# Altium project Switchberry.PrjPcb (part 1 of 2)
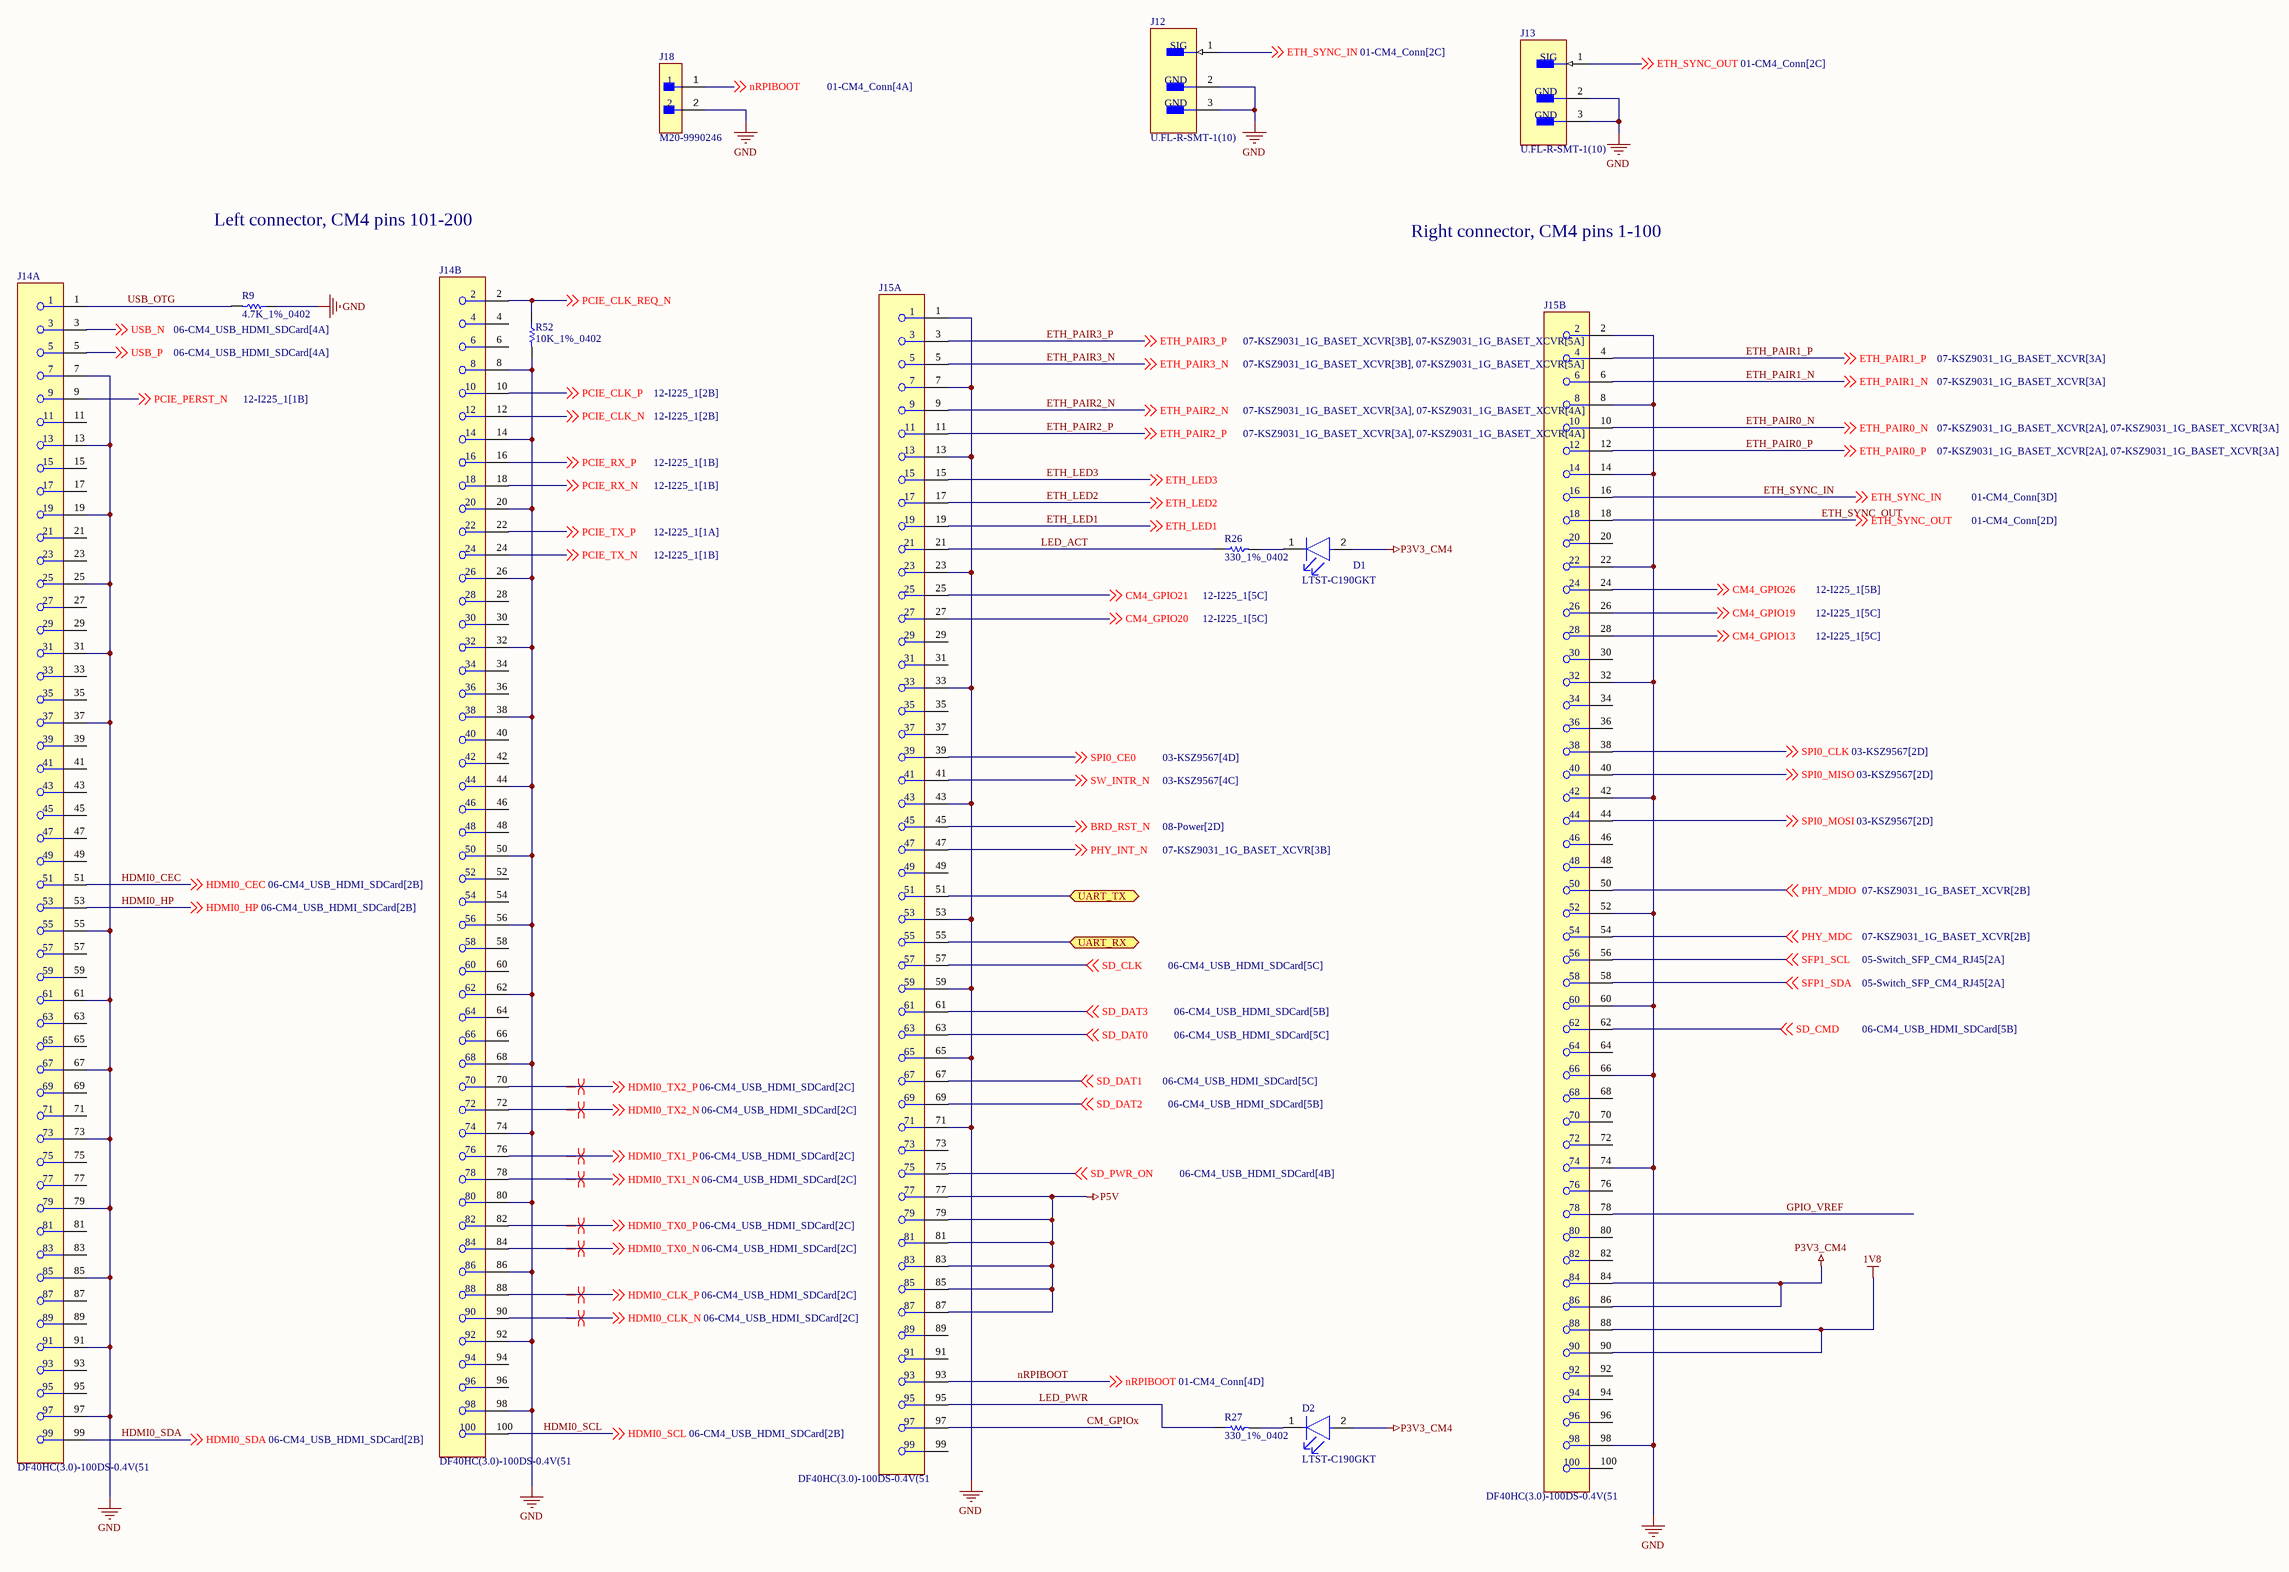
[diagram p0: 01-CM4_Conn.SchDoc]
13 sheets, 431 parts. Net scope: global (net labels, ports and power ports of the same name join across sheets).
Board file: Switchberry.PcbDoc
Sheets:
  01-CM4_Conn.SchDoc
  02-Clocks.SchDoc
  03-KSZ9567.SchDoc
  04-Switch_RJ45.SchDoc
  05-Switch_SFP_CM4_RJ45.SchDoc
  06-CM4_USB_HDMI_SDCard.SchDoc
  07-KSZ9031_1G_BASET_XCVR.SchDoc
  08-Power.SchDoc
  09-Switch_Power_Filters.SchDoc
  10-RJ45_Protection.SchDoc
  11-Switch_Strapping.SchDoc
  12-I225_1.SchDoc
  13-I225_2.SchDoc

## Sheet 01-CM4_Conn.SchDoc
size C; SheetNumber: 1; SheetTotal: 13

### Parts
D1  LTST-C190GKT  [FP-LTST-C190GKT-MFG]
D2  LTST-C190GKT  [FP-LTST-C190GKT-MFG]
J12  U.FL-R-SMT-1(10)  [FP-U_FL-R-SMT-1_10-MFG]
J13  U.FL-R-SMT-1(10)  [FP-U_FL-R-SMT-1_10-MFG]
J14  DF40HC(3.0)-100DS-0.4V(51  [FP-DF40HC_3_0_-100DS-0_4V-MFG]  (parts A,B of 2)
J15  DF40HC(3.0)-100DS-0.4V(51  [FP-DF40HC_3_0_-100DS-0_4V-MFG]  (parts A,B of 2)
J18  M20-9990246  [FP-M20-9990246-MFG]
R9  4.7K_1%_0402  [RESC1005X40X25NL10T10]
R26  330_1%_0402  [RESC1005X40X25NL10T10]
R27  330_1%_0402  [RESC1005X40X25NL10T10]
R52  10K_1%_0402  [RESC1005X40X25NL10T10]

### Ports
UART_RX (bidir), UART_TX (bidir)

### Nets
1V8: J15.88 J15.90
GND: J12.2(GND) J12.3(GND) J13.2(GND) J13.3(GND) J14.7 J14.8 J14.13 J14.14 J14.19 J14.20 J14.25 J14.26 J14.31 J14.32 J14.37 J14.38 J14.44 J14.50 J14.55 J14.56 J14.61 J14.62 J14.67 J14.68 J14.73 J14.74 J14.79 J14.80 J14.85 J14.86 J14.91 J14.92 J14.97 J14.98 J15.1 J15.2 J15.7 J15.8 J15.13 J15.14 J15.22 J15.23 J15.32 J15.33 J15.42 J15.43 J15.52 J15.53 J15.59 J15.60 J15.65 J15.66 J15.71 J15.74 J15.98 J18.2 R9.1 R52.2
P3V3_CM4: D1.2(A) D2.2(A) J15.84 J15.86
P5V: J15.77 J15.79 J15.81 J15.83 J15.85 J15.87
BRD_RST_N: J15.45 ; off-sheet BRD_RST_N
CM4_GPIO13: J15.28 ; off-sheet CM4_GPIO13
CM4_GPIO19: J15.26 ; off-sheet CM4_GPIO19
CM4_GPIO20: J15.27 ; off-sheet CM4_GPIO20
CM4_GPIO21: J15.25 ; off-sheet CM4_GPIO21
CM4_GPIO26: J15.24 ; off-sheet CM4_GPIO26
CM_GPIOx: J15.97
ETH_LED1: J15.19 ; off-sheet ETH_LED1
ETH_LED2: J15.17 ; off-sheet ETH_LED2
ETH_LED3: J15.15 ; off-sheet ETH_LED3
ETH_PAIR0_N: J15.10 ; off-sheet ETH_PAIR0_N
ETH_PAIR0_P: J15.12 ; off-sheet ETH_PAIR0_P
ETH_PAIR1_N: J15.6 ; off-sheet ETH_PAIR1_N
ETH_PAIR1_P: J15.4 ; off-sheet ETH_PAIR1_P
ETH_PAIR2_N: J15.9 ; off-sheet ETH_PAIR2_N
ETH_PAIR2_P: J15.11 ; off-sheet ETH_PAIR2_P
ETH_PAIR3_N: J15.5 ; off-sheet ETH_PAIR3_N
ETH_PAIR3_P: J15.3 ; off-sheet ETH_PAIR3_P
ETH_SYNC_IN: J12.1(SIG) J15.16 ; off-sheet ETH_SYNC_IN
ETH_SYNC_OUT: J13.1(SIG) J15.18 ; off-sheet ETH_SYNC_OUT
GPIO_VREF: J15.78
HDMI0_CEC: J14.51 ; off-sheet HDMI0_CEC
HDMI0_CLK_N: J14.90 ; off-sheet HDMI0_CLK_N
HDMI0_CLK_P: J14.88 ; off-sheet HDMI0_CLK_P
HDMI0_HP: J14.53 ; off-sheet HDMI0_HP
HDMI0_SCL: J14.100 ; off-sheet HDMI0_SCL
HDMI0_SDA: J14.99 ; off-sheet HDMI0_SDA
HDMI0_TX0_N: J14.84 ; off-sheet HDMI0_TX0_N
HDMI0_TX0_P: J14.82 ; off-sheet HDMI0_TX0_P
HDMI0_TX1_N: J14.78 ; off-sheet HDMI0_TX1_N
HDMI0_TX1_P: J14.76 ; off-sheet HDMI0_TX1_P
HDMI0_TX2_N: J14.72 ; off-sheet HDMI0_TX2_N
HDMI0_TX2_P: J14.70 ; off-sheet HDMI0_TX2_P
LED_ACT: J15.21 R26.1
LED_PWR: J15.95 R27.1
nRPIBOOT: J15.93 J18.1 ; off-sheet nRPIBOOT
PCIE_CLK_N: J14.12 ; off-sheet PCIE_CLK_N
PCIE_CLK_P: J14.10 ; off-sheet PCIE_CLK_P
PCIE_CLK_REQ_N: J14.2 R52.1 ; off-sheet PCIE_CLK_REQ_N
PCIE_PERST_N: J14.9 ; off-sheet PCIE_PERST_N
PCIE_RX_N: J14.18 ; off-sheet PCIE_RX_N
PCIE_RX_P: J14.16 ; off-sheet PCIE_RX_P
PCIE_TX_N: J14.24 ; off-sheet PCIE_TX_N
PCIE_TX_P: J14.22 ; off-sheet PCIE_TX_P
PHY_INT_N: J15.47 ; off-sheet PHY_INT_N
PHY_MDC: J15.54 ; off-sheet PHY_MDC
PHY_MDIO: J15.50 ; off-sheet PHY_MDIO
SD_CLK: J15.57 ; off-sheet SD_CLK
SD_CMD: J15.62 ; off-sheet SD_CMD
SD_DAT0: J15.63 ; off-sheet SD_DAT0
SD_DAT1: J15.67 ; off-sheet SD_DAT1
SD_DAT2: J15.69 ; off-sheet SD_DAT2
SD_DAT3: J15.61 ; off-sheet SD_DAT3
SD_PWR_ON: J15.75 ; off-sheet SD_PWR_ON
SFP1_SCL: J15.56 ; off-sheet SFP1_SCL
SFP1_SDA: J15.58 ; off-sheet SFP1_SDA
SPI0_CE0: J15.39 ; off-sheet SPI0_CE0
SPI0_CLK: J15.38 ; off-sheet SPI0_CLK
SPI0_MISO: J15.40 ; off-sheet SPI0_MISO
SPI0_MOSI: J15.44 ; off-sheet SPI0_MOSI
SW_INTR_N: J15.41 ; off-sheet SW_INTR_N
USB_N: J14.3 ; off-sheet USB_N
USB_OTG: J14.1 R9.2
USB_P: J14.5 ; off-sheet USB_P
NetD1_1: D1.1(C) R26.2
NetD2_1: D2.1(C) R27.2
NetJ15_51: J15.51 ; port UART_TX
NetJ15_55: J15.55 ; port UART_RX

Not connected (* = marked no-connect by the designer): J14 4 6 11 15 17 21 23 27 28 29 30 33 34 35 36 39 40 41 42 43 45 46 47 48 49 52 54 57 58 59 60 63 64 65 66 69 71 75 77 81 83 87 89 93 94 95 96; J15 20 29 30 31 34 35 36 37 46 48 49 64 68 70 72 73 76 80 82 89 91 92 94 96 99 100

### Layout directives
differential pair: HDMI0_CLK_N, HDMI0_CLK_P, HDMI0_TX0_N, HDMI0_TX0_P, HDMI0_TX1_N, HDMI0_TX1_P, HDMI0_TX2_N, HDMI0_TX2_P

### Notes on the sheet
- Left connector, CM4 pins 101-200
- Right connector, CM4 pins 1-100

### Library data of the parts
D1 D2 = CMP-22017-000005-2: LED GREEN CLEAR CHIP SMD; Dominant Wavelength: 569nm; Reverse Voltage: 5V; Lens Color: Colorless; Viewing Angle: 130°; Voltage: 2V; Forward Current: 30mA; Power Dissipation: 100mW; Luminous Intensity: 6mcd; Number of LEDs: 1; Forward Voltage: 2.1V; Wavelength: 565nm; Test Current: 10mA
J12 J13 = CMP-2000-05152-3: CONN U.FL RCPT STR 50 OHM SMD; Max Frequency: 6GHz; Connector Type: Coaxial; Body Plating: Silver; Body Material: Bronze; Impedance: 50R; Dielectric Material: Polymer; Insulation Resistance: 500MR; Gender: Male
J14 J15 = CMP-11605-000071-1: CONN RCPT 100POS SMD GOLD; Pitch: 0.016inch; Number of Positions: 100; Connector Type: Receptacle
J18 = CMP-15831-000009-1: CONN HEADER VERT 2POS 2.54MM; Manufacturer: Harwin; Conn Gender: Male; Conn Orientation: Vertical; Number Of Contacts: 2; Current Rating: 3A
R9 = CMP-2002-05217-1: Manufacturer: Bourns; Part Number: CR0402-FX-4701GLF
R26 R27 = CMP-2002-05853-1: Manufacturer: Panasonic; Part Number: ERA-2AED331X
R52 = CMP-2002-04694-1: Manufacturer: Bourns; Part Number: CR0402-FX-1002GLF

## Sheet 02-Clocks.SchDoc
size A; SheetNumber: 2; SheetTotal: 11
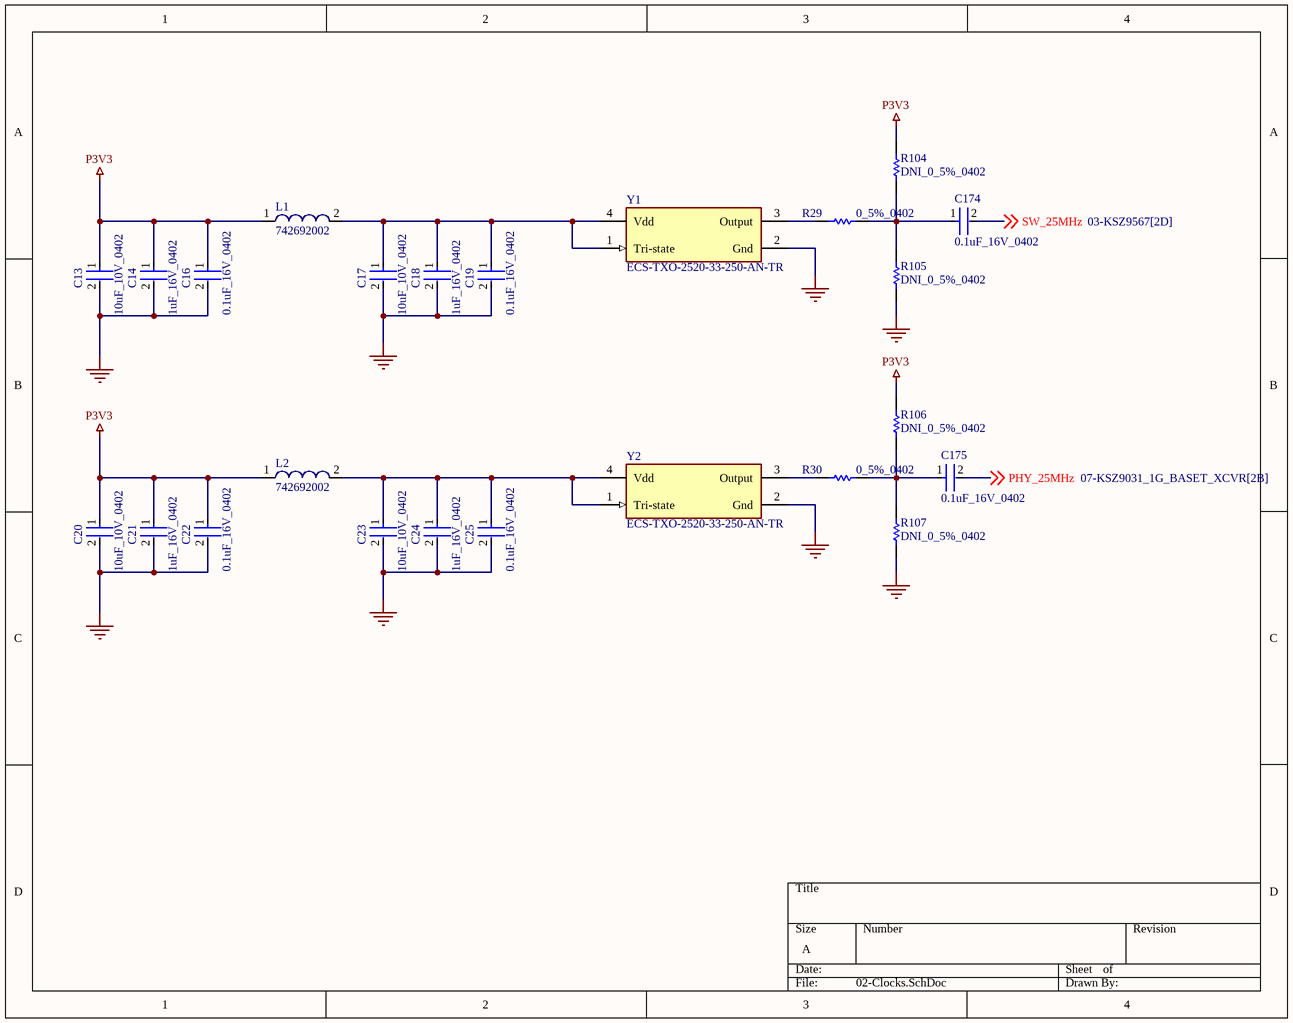
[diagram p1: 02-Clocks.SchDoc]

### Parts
C13  10uF_10V_0402  [FP-CL05A106MP5NUNC-MFG]
C14  1uF_16V_0402  [FP-0402-L_1_0_0_05-W_0_5-IPC_A]
C16  0.1uF_16V_0402  [FP-C0402-BB-MFG]
C17  10uF_10V_0402  [FP-CL05A106MP5NUNC-MFG]
C18  1uF_16V_0402  [FP-0402-L_1_0_0_05-W_0_5-IPC_A]
C19  0.1uF_16V_0402  [FP-C0402-BB-MFG]
C20  10uF_10V_0402  [FP-CL05A106MP5NUNC-MFG]
C21  1uF_16V_0402  [FP-0402-L_1_0_0_05-W_0_5-IPC_A]
C22  0.1uF_16V_0402  [FP-C0402-BB-MFG]
C23  10uF_10V_0402  [FP-CL05A106MP5NUNC-MFG]
C24  1uF_16V_0402  [FP-0402-L_1_0_0_05-W_0_5-IPC_A]
C25  0.1uF_16V_0402  [FP-C0402-BB-MFG]
C174  0.1uF_16V_0402  [FP-C0402-BB-MFG]
C175  0.1uF_16V_0402  [FP-C0402-BB-MFG]
L1  742692002  [WE-TMSB 0201]
L2  742692002  [WE-TMSB 0201]
R29  0_5%_0402  [RESC1005X40X25NL05T10]
R30  0_5%_0402  [RESC1005X40X25NL05T10]
R104  DNI_0_5%_0402  [RESC1005X40X25NL05T10]  (no BOM)
R105  DNI_0_5%_0402  [RESC1005X40X25NL05T10]  (no BOM)
R106  DNI_0_5%_0402  [RESC1005X40X25NL05T10]  (no BOM)
R107  DNI_0_5%_0402  [RESC1005X40X25NL05T10]  (no BOM)
Y1  ECS-TXO-2520-33-250-AN-TR  [FP-ECS-TXO-2520-MFG]
Y2  ECS-TXO-2520-33-250-AN-TR  [FP-ECS-TXO-2520-MFG]

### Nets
GND: C13.2 C14.2 C16.2 C17.2 C18.2 C19.2 C20.2 C21.2 C22.2 C23.2 C24.2 C25.2 R105.1 R107.1 Y1.2(Gnd) Y2.2(Gnd)
P3V3: C13.1 C14.1 C16.1 C20.1 C21.1 C22.1 L1.1 L2.1 R104.2 R106.2
PHY_25MHz: C175.2 ; off-sheet PHY_25MHz
SW_25MHz: C174.2 ; off-sheet SW_25MHz
NetC17_1: C17.1 C18.1 C19.1 L1.2 Y1.1(Tri-state) Y1.4(Vdd)
NetC23_1: C23.1 C24.1 C25.1 L2.2 Y2.1(Tri-state) Y2.4(Vdd)
NetC174_1: C174.1 R29.2 R104.1 R105.2
NetC175_1: C175.1 R30.2 R106.1 R107.2
NetR29_1: R29.1 Y1.3(Output)
NetR30_1: R30.1 Y2.3(Output)

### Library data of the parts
C13 C17 C20 C23 = CMP-13271-000002-1: CAP CER 10UF 10V X5R 0402; Manufacturer Part Number: CL05A106MP5NUNC; Manufacturer: Samsung; Temperature Coefficient: 15%; Tolerance: 20%; Material: Ceramic
C14 C18 C21 C24 = CMP-14477-000104-2: None; Tolerance: 10%; Voltage Rating: 16V; Dielectric: X5R; Capacitance: 1uF
C16 C19 C22 C25 C174 C175 = CMP-1034-02068-3: CAP CER 0.1UF 16V 5% X7R 0402; Manufacturer: Kemet; Manufacturer Part Number: C0402C104J4RACTU; Value: 0.10 μF; Temperature Coefficient: 15%; Tolerance: 0.05; Material: Ceramic
L1 L2 = CMP-1490-00001-1: Tiny Multilayer Suppression  Bead  WE-TMSB, Z= 60 Ohm; Manufacturer: Wuerth Elektronik; Impedance: 60 Ohm
R29 R30 R104-R107 = CMP-2002-06457-1: Manufacturer: Panasonic; Part Number: ERJ-U020R00X
Y1 Y2 = CMP-40224-000034-1: XTAL OSC TCXO 25.0000MHZ HCMOS

## Sheet 03-KSZ9567.SchDoc
size B; SheetNumber: 3; SheetTotal: 11
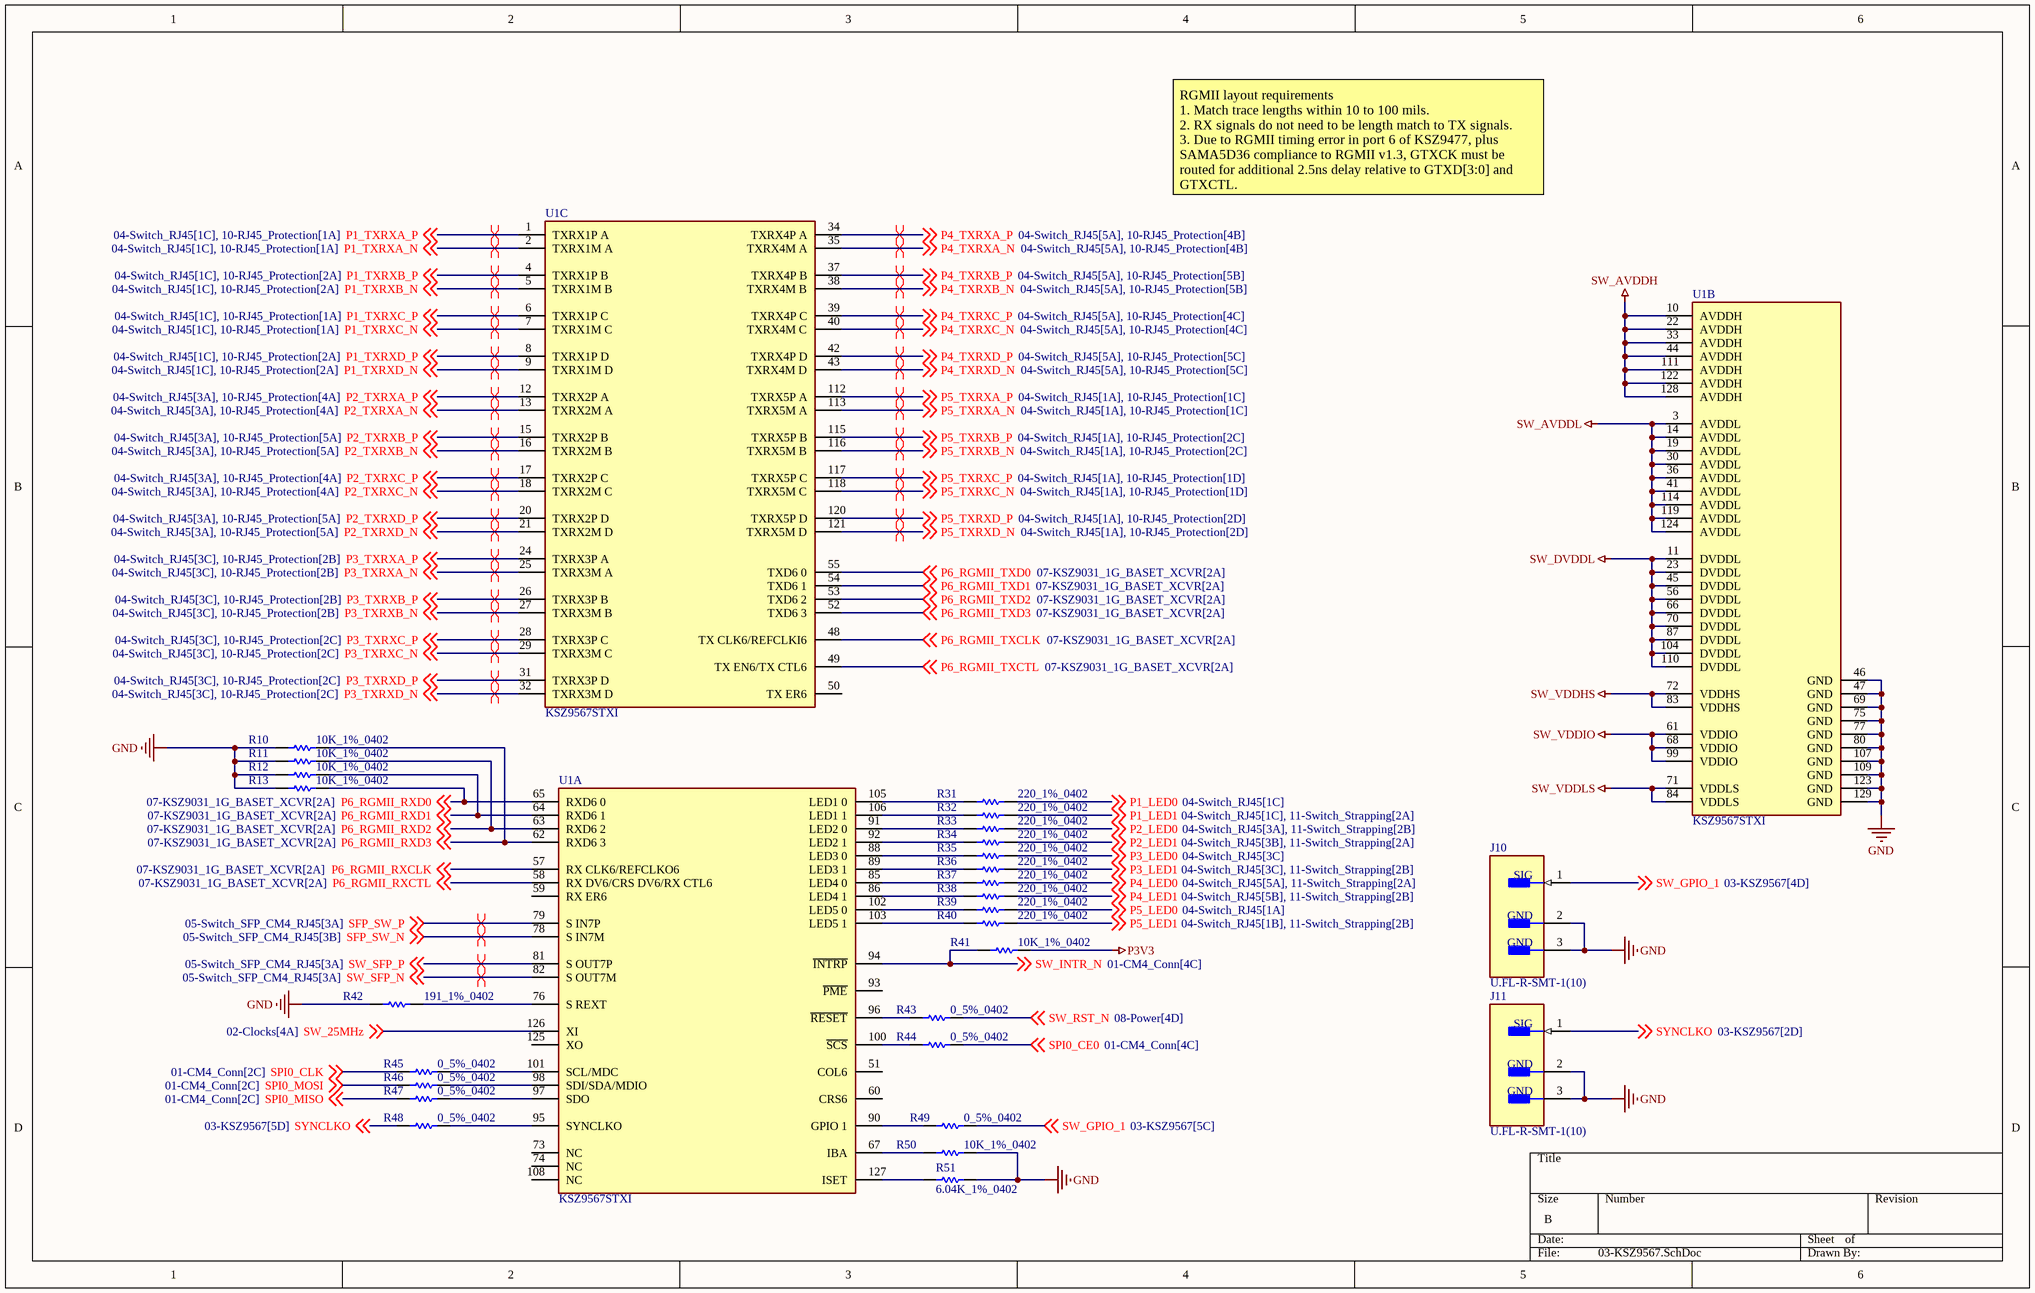
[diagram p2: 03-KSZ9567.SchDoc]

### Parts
J10  U.FL-R-SMT-1(10)  [FP-U_FL-R-SMT-1_10-MFG]
J11  U.FL-R-SMT-1(10)  [FP-U_FL-R-SMT-1_10-MFG]
R10  10K_1%_0402  [RESC1005X40X25NL10T10]
R11  10K_1%_0402  [RESC1005X40X25NL10T10]
R12  10K_1%_0402  [RESC1005X40X25NL10T10]
R13  10K_1%_0402  [RESC1005X40X25NL10T10]
R31  220_1%_0402  [RESC1005X40X25NL05T10]
R32  220_1%_0402  [RESC1005X40X25NL05T10]
R33  220_1%_0402  [RESC1005X40X25NL05T10]
R34  220_1%_0402  [RESC1005X40X25NL05T10]
R35  220_1%_0402  [RESC1005X40X25NL05T10]
R36  220_1%_0402  [RESC1005X40X25NL05T10]
R37  220_1%_0402  [RESC1005X40X25NL05T10]
R38  220_1%_0402  [RESC1005X40X25NL05T10]
R39  220_1%_0402  [RESC1005X40X25NL05T10]
R40  220_1%_0402  [RESC1005X40X25NL05T10]
R41  10K_1%_0402  [RESC1005X40X25NL10T10]
R42  191_1%_0402  [RESC1005X40X25LL10T10]
R43  0_5%_0402  [RESC1005X40X25NL05T10]
R44  0_5%_0402  [RESC1005X40X25NL05T10]
R45  0_5%_0402  [RESC1005X40X25NL05T10]
R46  0_5%_0402  [RESC1005X40X25NL05T10]
R47  0_5%_0402  [RESC1005X40X25NL05T10]
R48  0_5%_0402  [RESC1005X40X25NL05T10]
R49  0_5%_0402  [RESC1005X40X25NL05T10]
R50  10K_1%_0402  [RESC1005X40X25NL10T10]
R51  6.04K_1%_0402  [RESC1005X40X25NL10T10]
U1  KSZ9567STXI  [FP-C04-418-IPC_A]  (parts A,B,C of 3)

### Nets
GND: J10.2(GND) J10.3(GND) J11.2(GND) J11.3(GND) R10.1 R11.1 R12.1 R13.1 R42.1 R50.2 R51.2 U1.46(GND) U1.47(GND) U1.69(GND) U1.75(GND) U1.77(GND) U1.80(GND) U1.107(GND) U1.109(GND) U1.123(GND) U1.129(GND)
P3V3: R41.2
SW_AVDDH: U1.10(AVDDH) U1.22(AVDDH) U1.33(AVDDH) U1.44(AVDDH) U1.111(AVDDH) U1.122(AVDDH) U1.128(AVDDH)
SW_AVDDL: U1.3(AVDDL) U1.14(AVDDL) U1.19(AVDDL) U1.30(AVDDL) U1.36(AVDDL) U1.41(AVDDL) U1.114(AVDDL) U1.119(AVDDL) U1.124(AVDDL)
SW_DVDDL: U1.11(DVDDL) U1.23(DVDDL) U1.45(DVDDL) U1.56(DVDDL) U1.66(DVDDL) U1.70(DVDDL) U1.87(DVDDL) U1.104(DVDDL) U1.110(DVDDL)
SW_VDDHS: U1.72(VDDHS) U1.83(VDDHS)
SW_VDDIO: U1.61(VDDIO) U1.68(VDDIO) U1.99(VDDIO)
SW_VDDLS: U1.71(VDDLS) U1.84(VDDLS)
P1_LED0: R31.2 ; off-sheet P1_LED0
P1_LED1: R32.2 ; off-sheet P1_LED1
P1_TXRXA_N: U1.2(TXRX1M_A) ; off-sheet P1_TXRXA_N
P1_TXRXA_P: U1.1(TXRX1P_A) ; off-sheet P1_TXRXA_P
P1_TXRXB_N: U1.5(TXRX1M_B) ; off-sheet P1_TXRXB_N
P1_TXRXB_P: U1.4(TXRX1P_B) ; off-sheet P1_TXRXB_P
P1_TXRXC_N: U1.7(TXRX1M_C) ; off-sheet P1_TXRXC_N
P1_TXRXC_P: U1.6(TXRX1P_C) ; off-sheet P1_TXRXC_P
P1_TXRXD_N: U1.9(TXRX1M_D) ; off-sheet P1_TXRXD_N
P1_TXRXD_P: U1.8(TXRX1P_D) ; off-sheet P1_TXRXD_P
P2_LED0: R33.2 ; off-sheet P2_LED0
P2_LED1: R34.2 ; off-sheet P2_LED1
P2_TXRXA_N: U1.13(TXRX2M_A) ; off-sheet P2_TXRXA_N
P2_TXRXA_P: U1.12(TXRX2P_A) ; off-sheet P2_TXRXA_P
P2_TXRXB_N: U1.16(TXRX2M_B) ; off-sheet P2_TXRXB_N
P2_TXRXB_P: U1.15(TXRX2P_B) ; off-sheet P2_TXRXB_P
P2_TXRXC_N: U1.18(TXRX2M_C) ; off-sheet P2_TXRXC_N
P2_TXRXC_P: U1.17(TXRX2P_C) ; off-sheet P2_TXRXC_P
P2_TXRXD_N: U1.21(TXRX2M_D) ; off-sheet P2_TXRXD_N
P2_TXRXD_P: U1.20(TXRX2P_D) ; off-sheet P2_TXRXD_P
P3_LED0: R35.2 ; off-sheet P3_LED0
P3_LED1: R36.2 ; off-sheet P3_LED1
P3_TXRXA_N: U1.25(TXRX3M_A) ; off-sheet P3_TXRXA_N
P3_TXRXA_P: U1.24(TXRX3P_A) ; off-sheet P3_TXRXA_P
P3_TXRXB_N: U1.27(TXRX3M_B) ; off-sheet P3_TXRXB_N
P3_TXRXB_P: U1.26(TXRX3P_B) ; off-sheet P3_TXRXB_P
P3_TXRXC_N: U1.29(TXRX3M_C) ; off-sheet P3_TXRXC_N
P3_TXRXC_P: U1.28(TXRX3P_C) ; off-sheet P3_TXRXC_P
P3_TXRXD_N: U1.32(TXRX3M_D) ; off-sheet P3_TXRXD_N
P3_TXRXD_P: U1.31(TXRX3P_D) ; off-sheet P3_TXRXD_P
P4_LED0: R37.2 ; off-sheet P4_LED0
P4_LED1: R38.2 ; off-sheet P4_LED1
P4_TXRXA_N: U1.35(TXRX4M_A) ; off-sheet P4_TXRXA_N
P4_TXRXA_P: U1.34(TXRX4P_A) ; off-sheet P4_TXRXA_P
P4_TXRXB_N: U1.38(TXRX4M_B) ; off-sheet P4_TXRXB_N
P4_TXRXB_P: U1.37(TXRX4P_B) ; off-sheet P4_TXRXB_P
P4_TXRXC_N: U1.40(TXRX4M_C) ; off-sheet P4_TXRXC_N
P4_TXRXC_P: U1.39(TXRX4P_C) ; off-sheet P4_TXRXC_P
P4_TXRXD_N: U1.43(TXRX4M_D) ; off-sheet P4_TXRXD_N
P4_TXRXD_P: U1.42(TXRX4P_D) ; off-sheet P4_TXRXD_P
P5_LED0: R39.2 ; off-sheet P5_LED0
P5_LED1: R40.2 ; off-sheet P5_LED1
P5_TXRXA_N: U1.113(TXRX5M_A) ; off-sheet P5_TXRXA_N
P5_TXRXA_P: U1.112(TXRX5P_A) ; off-sheet P5_TXRXA_P
P5_TXRXB_N: U1.116(TXRX5M_B) ; off-sheet P5_TXRXB_N
P5_TXRXB_P: U1.115(TXRX5P_B) ; off-sheet P5_TXRXB_P
P5_TXRXC_N: U1.118(TXRX5M_C) ; off-sheet P5_TXRXC_N
P5_TXRXC_P: U1.117(TXRX5P_C) ; off-sheet P5_TXRXC_P
P5_TXRXD_N: U1.121(TXRX5M_D) ; off-sheet P5_TXRXD_N
P5_TXRXD_P: U1.120(TXRX5P_D) ; off-sheet P5_TXRXD_P
P6_RGMII_RXCLK: U1.57(RX_CLK6/REFCLKO6) ; off-sheet P6_RGMII_RXCLK
P6_RGMII_RXCTL: U1.58(RX_DV6/CRS_DV6/RX_CTL6) ; off-sheet P6_RGMII_RXCTL
P6_RGMII_RXD0: R13.2 U1.65(RXD6_0) ; off-sheet P6_RGMII_RXD0
P6_RGMII_RXD1: R12.2 U1.64(RXD6_1) ; off-sheet P6_RGMII_RXD1
P6_RGMII_RXD2: R11.2 U1.63(RXD6_2) ; off-sheet P6_RGMII_RXD2
P6_RGMII_RXD3: R10.2 U1.62(RXD6_3) ; off-sheet P6_RGMII_RXD3
P6_RGMII_TXCLK: U1.48(TX_CLK6/REFCLKI6) ; off-sheet P6_RGMII_TXCLK
P6_RGMII_TXCTL: U1.49(TX_EN6/TX_CTL6) ; off-sheet P6_RGMII_TXCTL
P6_RGMII_TXD0: U1.55(TXD6_0) ; off-sheet P6_RGMII_TXD0
P6_RGMII_TXD1: U1.54(TXD6_1) ; off-sheet P6_RGMII_TXD1
P6_RGMII_TXD2: U1.53(TXD6_2) ; off-sheet P6_RGMII_TXD2
P6_RGMII_TXD3: U1.52(TXD6_3) ; off-sheet P6_RGMII_TXD3
SFP_SW_N: U1.78(S_IN7M) ; off-sheet SFP_SW_N
SFP_SW_P: U1.79(S_IN7P) ; off-sheet SFP_SW_P
SPI0_CE0: R44.2 ; off-sheet SPI0_CE0
SPI0_CLK: R45.1 ; off-sheet SPI0_CLK
SPI0_MISO: R47.1 ; off-sheet SPI0_MISO
SPI0_MOSI: R46.1 ; off-sheet SPI0_MOSI
SW_25MHz: U1.126(XI) ; off-sheet SW_25MHz
SW_GPIO_1: J10.1(SIG) R49.2 ; off-sheet SW_GPIO_1
SW_INTR_N: R41.1 U1.94(~{INTRP}) ; off-sheet SW_INTR_N
SW_RST_N: R43.2 ; off-sheet SW_RST_N
SW_SFP_N: U1.82(S_OUT7M) ; off-sheet SW_SFP_N
SW_SFP_P: U1.81(S_OUT7P) ; off-sheet SW_SFP_P
SYNCLKO: J11.1(SIG) R48.1 ; off-sheet SYNCLKO
NetR31_1: R31.1 U1.105(LED1_0)
NetR32_1: R32.1 U1.106(LED1_1)
NetR33_1: R33.1 U1.91(LED2_0)
NetR34_1: R34.1 U1.92(LED2_1)
NetR35_1: R35.1 U1.88(LED3_0)
NetR36_1: R36.1 U1.89(LED3_1)
NetR37_1: R37.1 U1.85(LED4_0)
NetR38_1: R38.1 U1.86(LED4_1)
NetR39_1: R39.1 U1.102(LED5_0)
NetR40_1: R40.1 U1.103(LED5_1)
NetR42_2: R42.2 U1.76(S_REXT)
NetR43_1: R43.1 U1.96(~{RESET})
NetR44_1: R44.1 U1.100(~{SCS})
NetR45_2: R45.2 U1.101(SCL/MDC)
NetR46_2: R46.2 U1.98(SDI/SDA/MDIO)
NetR47_2: R47.2 U1.97(SDO)
NetR48_2: R48.2 U1.95(SYNCLKO)
NetR49_1: R49.1 U1.90(GPIO_1)
NetR50_1: R50.1 U1.67(IBA)
NetR51_1: R51.1 U1.127(ISET)

Not connected (* = marked no-connect by the designer): U1 50(TX_ER6) 51(COL6) 59(RX_ER6) 60(CRS6) 73(NC) 74(NC) 93(~{PME}) 108(NC) 125(XO)

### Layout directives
differential pair: P1_TXRXA_N, P1_TXRXA_P, P1_TXRXB_N, P1_TXRXB_P, P1_TXRXC_N, P1_TXRXC_P, P1_TXRXD_N, P1_TXRXD_P, P2_TXRXA_N, P2_TXRXA_P, P2_TXRXB_N, P2_TXRXB_P, P2_TXRXC_N, P2_TXRXC_P, P2_TXRXD_N, P2_TXRXD_P, P3_TXRXA_N, P3_TXRXA_P, P3_TXRXB_N, P3_TXRXB_P, P3_TXRXC_N, P3_TXRXC_P, P3_TXRXD_N, P3_TXRXD_P, P4_TXRXA_N, P4_TXRXA_P, P4_TXRXB_N, P4_TXRXB_P, P4_TXRXC_N, P4_TXRXC_P, P4_TXRXD_N, P4_TXRXD_P, P5_TXRXA_N, P5_TXRXA_P, P5_TXRXB_N, P5_TXRXB_P, P5_TXRXC_N, P5_TXRXC_P, P5_TXRXD_N, P5_TXRXD_P, SFP_SW_N, SFP_SW_P, SW_SFP_N, SW_SFP_P

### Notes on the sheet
- RGMII layout requirements
  1. Match trace lengths within 10 to 100 mils.
  2. RX signals do not need to be length match to TX signals.
  3. Due to RGMII timing error in port 6 of KSZ9477, plus SAMA5D36 compliance to RGMII v1.3, GTXCK must be routed for additional 2.5ns delay relative to GTXD[3:0] and GTXCTL.

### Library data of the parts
J10 J11 = CMP-2000-05152-3: as J12 on sheet 01-CM4_Conn
R10-R13 R41 R50 = CMP-2002-04694-1: as R52 on sheet 01-CM4_Conn
R31-R40 = CMP-2002-07959-1: Manufacturer: Yageo / Phycomp; Part Number: RC0402JR-07220RL
R42 = CMP-2002-04891-1: Manufacturer: Bourns; Part Number: CR0402-FX-1910GLF
R43-R49 = CMP-2002-06457-1: as R29 on sheet 02-Clocks
R51 = CMP-2002-06319-1: Manufacturer: Multicomp; Part Number: MC00625W040216K04
U1 = CMP-06281-000207-1: IC ETHERNET SWITCH 7PORT 128TQFP; Interface: I2C

## Sheet 04-Switch_RJ45.SchDoc
size C; SheetNumber: 4; SheetTotal: 13
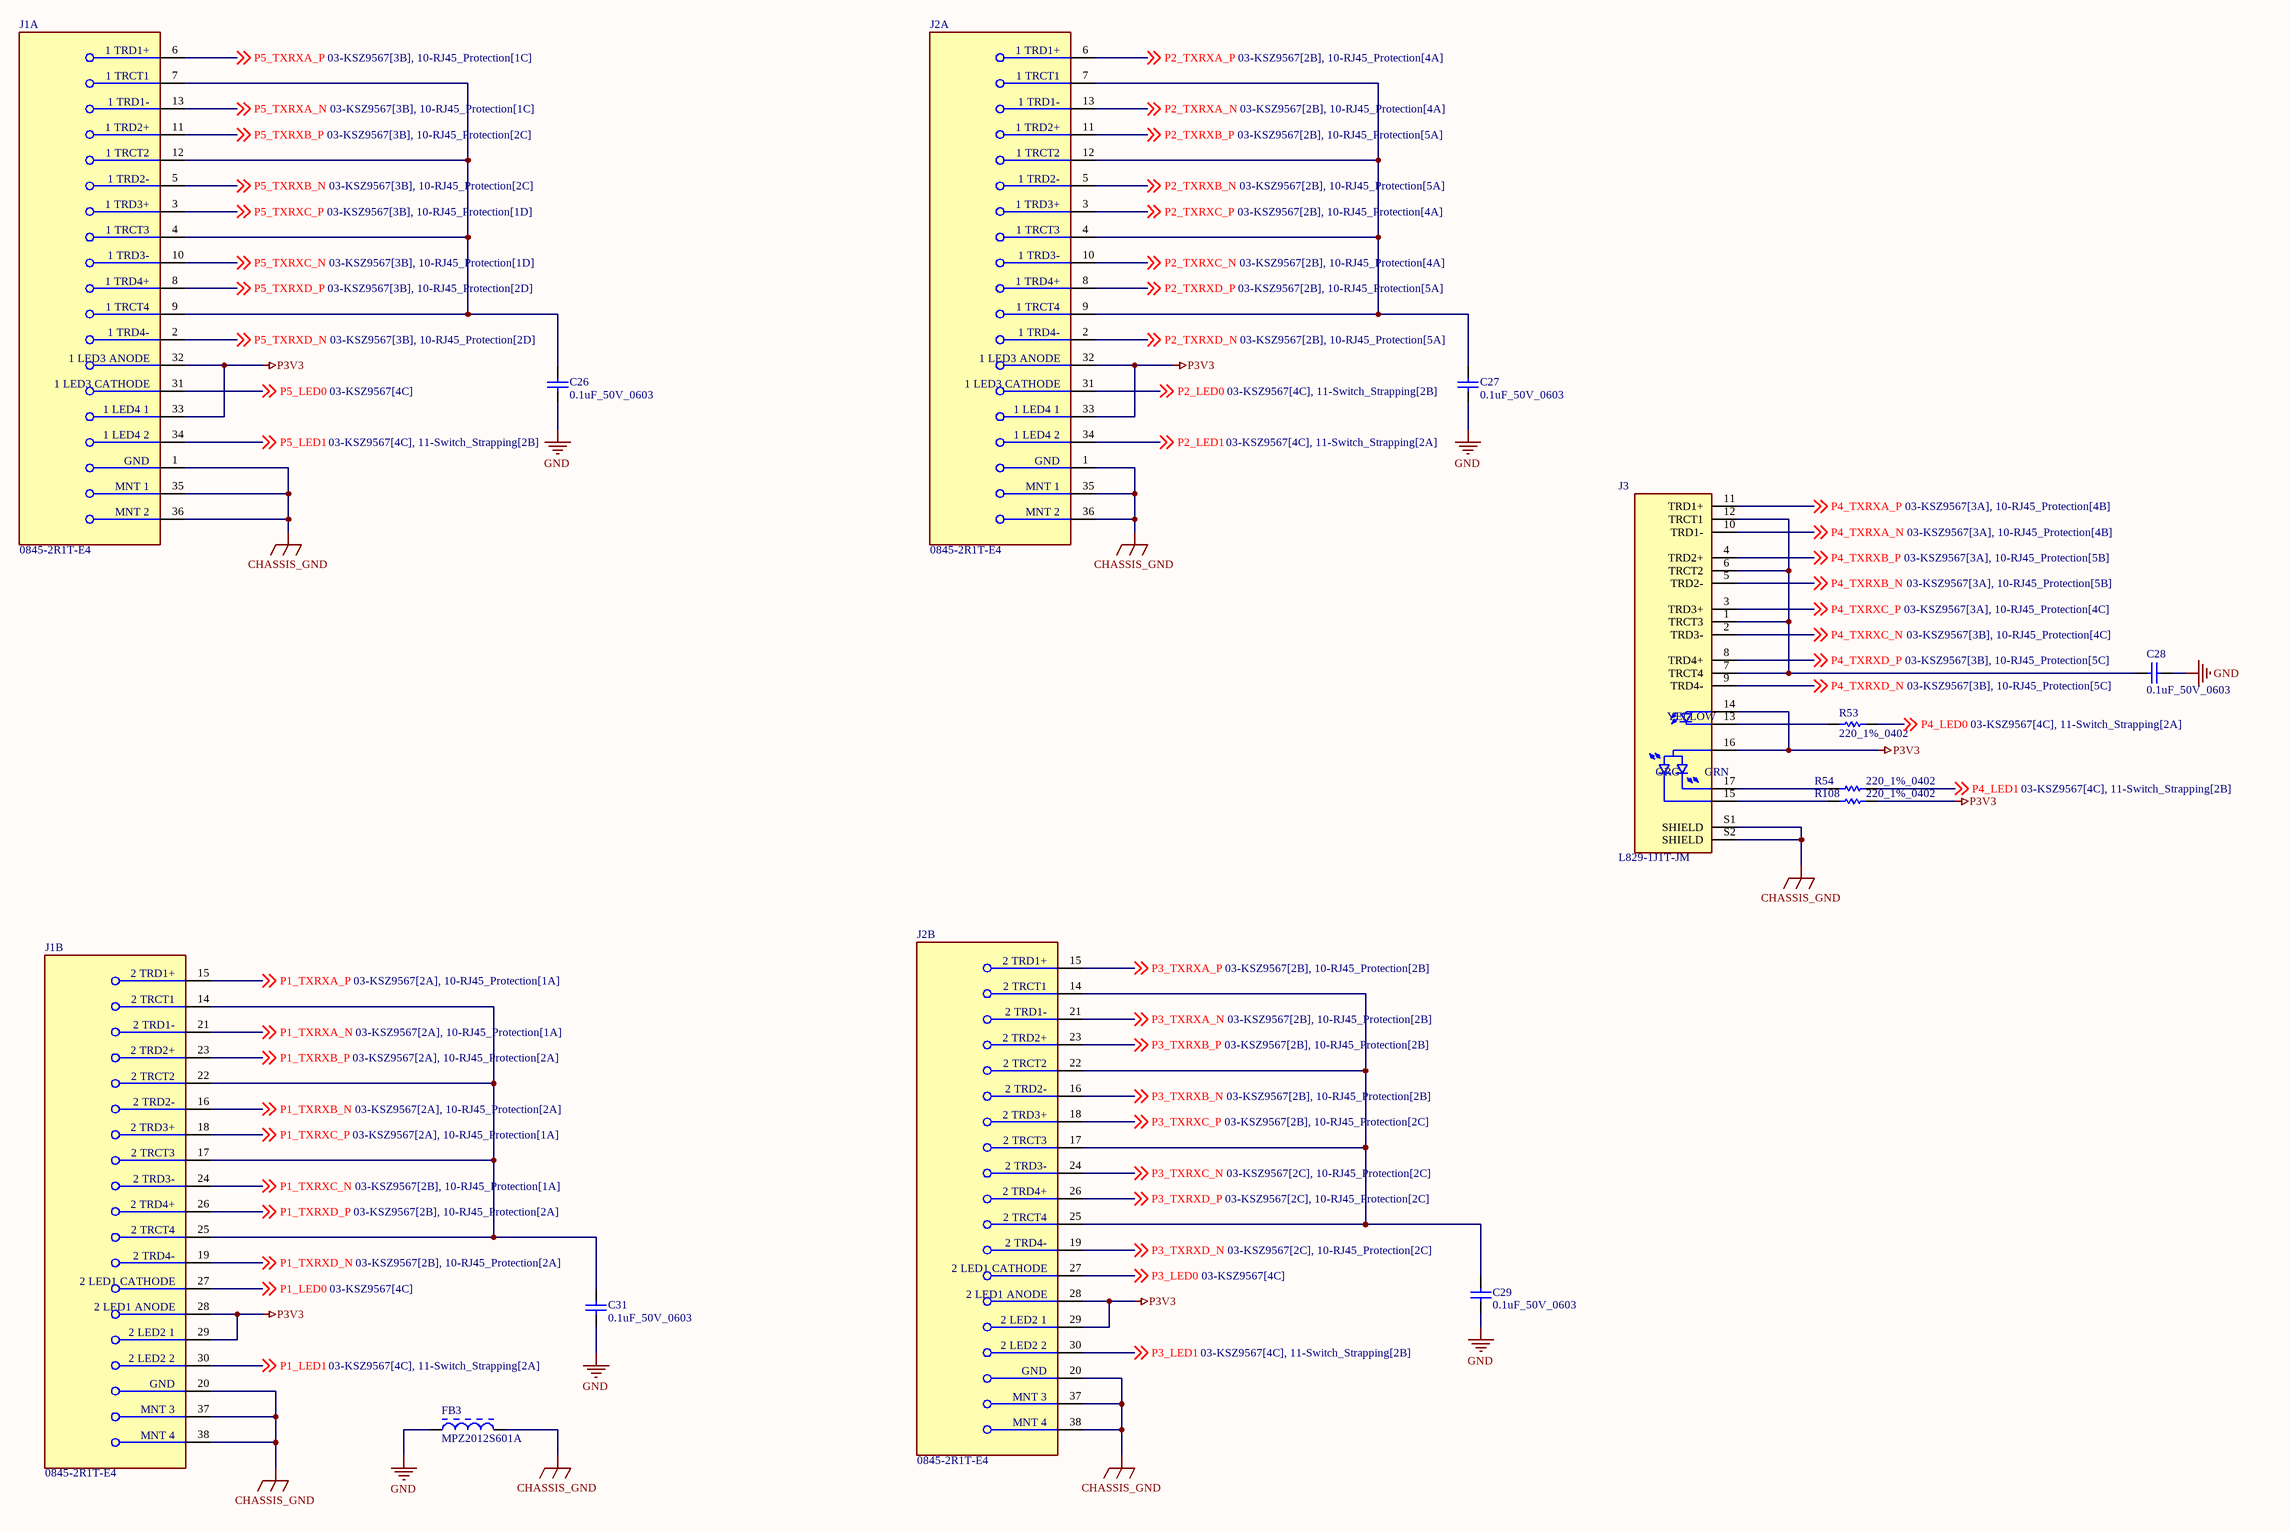
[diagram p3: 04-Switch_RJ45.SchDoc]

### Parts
C26  0.1uF_50V_0603  [CAPC1608X90X35ML10T15]
C27  0.1uF_50V_0603  [CAPC1608X90X35ML10T15]
C28  0.1uF_50V_0603  [CAPC1608X90X35ML10T15]
C29  0.1uF_50V_0603  [CAPC1608X90X35ML10T15]
C31  0.1uF_50V_0603  [CAPC1608X90X35ML10T15]
FB3  MPZ2012S601A  [TDK-MPZ2012_V]
J1  0845-2R1T-E4  [FP-0845-2R1T-E4-MFG]  (parts A,B of 2)
J2  0845-2R1T-E4  [FP-0845-2R1T-E4-MFG]  (parts A,B of 2)
J3  L829-1J1T-JM  [BEL_L829-1J1T-JM]
R53  220_1%_0402  [RESC1005X40X25LL10T10]
R54  220_1%_0402  [RESC1005X40X25LL10T10]
R108  220_1%_0402  [RESC1005X40X25LL10T10]

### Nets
CHASSIS_GND: FB3.2 J1.1(GND) J1.20(GND) J1.35(MNT_1) J1.36(MNT_2) J1.37(MNT_3) J1.38(MNT_4) J2.1(GND) J2.20(GND) J2.35(MNT_1) J2.36(MNT_2) J2.37(MNT_3) J2.38(MNT_4) J3.S1(SHIELD) J3.S2(SHIELD)
GND: C26.1 C27.1 C28.1 C29.1 C31.1 FB3.1
P3V3: J1.28(2_LED1_ANODE) J1.29(2_LED2_1) J1.32(1_LED3_ANODE) J1.33(1_LED4_1) J2.28(2_LED1_ANODE) J2.29(2_LED2_1) J2.32(1_LED3_ANODE) J2.33(1_LED4_1) J3.14(YA_1) J3.16(CA) R108.2
P1_LED0: J1.27(2_LED1_CATHODE) ; off-sheet P1_LED0
P1_LED1: J1.30(2_LED2_2) ; off-sheet P1_LED1
P1_TXRXA_N: J1.21(2_TRD1-) ; off-sheet P1_TXRXA_N
P1_TXRXA_P: J1.15(2_TRD1+) ; off-sheet P1_TXRXA_P
P1_TXRXB_N: J1.16(2_TRD2-) ; off-sheet P1_TXRXB_N
P1_TXRXB_P: J1.23(2_TRD2+) ; off-sheet P1_TXRXB_P
P1_TXRXC_N: J1.24(2_TRD3-) ; off-sheet P1_TXRXC_N
P1_TXRXC_P: J1.18(2_TRD3+) ; off-sheet P1_TXRXC_P
P1_TXRXD_N: J1.19(2_TRD4-) ; off-sheet P1_TXRXD_N
P1_TXRXD_P: J1.26(2_TRD4+) ; off-sheet P1_TXRXD_P
P2_LED0: J2.31(1_LED3_CATHODE) ; off-sheet P2_LED0
P2_LED1: J2.34(1_LED4_2) ; off-sheet P2_LED1
P2_TXRXA_N: J2.13(1_TRD1-) ; off-sheet P2_TXRXA_N
P2_TXRXA_P: J2.6(1_TRD1+) ; off-sheet P2_TXRXA_P
P2_TXRXB_N: J2.5(1_TRD2-) ; off-sheet P2_TXRXB_N
P2_TXRXB_P: J2.11(1_TRD2+) ; off-sheet P2_TXRXB_P
P2_TXRXC_N: J2.10(1_TRD3-) ; off-sheet P2_TXRXC_N
P2_TXRXC_P: J2.3(1_TRD3+) ; off-sheet P2_TXRXC_P
P2_TXRXD_N: J2.2(1_TRD4-) ; off-sheet P2_TXRXD_N
P2_TXRXD_P: J2.8(1_TRD4+) ; off-sheet P2_TXRXD_P
P3_LED0: J2.27(2_LED1_CATHODE) ; off-sheet P3_LED0
P3_LED1: J2.30(2_LED2_2) ; off-sheet P3_LED1
P3_TXRXA_N: J2.21(2_TRD1-) ; off-sheet P3_TXRXA_N
P3_TXRXA_P: J2.15(2_TRD1+) ; off-sheet P3_TXRXA_P
P3_TXRXB_N: J2.16(2_TRD2-) ; off-sheet P3_TXRXB_N
P3_TXRXB_P: J2.23(2_TRD2+) ; off-sheet P3_TXRXB_P
P3_TXRXC_N: J2.24(2_TRD3-) ; off-sheet P3_TXRXC_N
P3_TXRXC_P: J2.18(2_TRD3+) ; off-sheet P3_TXRXC_P
P3_TXRXD_N: J2.19(2_TRD4-) ; off-sheet P3_TXRXD_N
P3_TXRXD_P: J2.26(2_TRD4+) ; off-sheet P3_TXRXD_P
P4_LED0: R53.2 ; off-sheet P4_LED0
P4_LED1: R54.2 ; off-sheet P4_LED1
P4_TXRXA_N: J3.10(TRD1-) ; off-sheet P4_TXRXA_N
P4_TXRXA_P: J3.11(TRD1+) ; off-sheet P4_TXRXA_P
P4_TXRXB_N: J3.5(TRD2-) ; off-sheet P4_TXRXB_N
P4_TXRXB_P: J3.4(TRD2+) ; off-sheet P4_TXRXB_P
P4_TXRXC_N: J3.2(TRD3-) ; off-sheet P4_TXRXC_N
P4_TXRXC_P: J3.3(TRD3+) ; off-sheet P4_TXRXC_P
P4_TXRXD_N: J3.9(TRD4-) ; off-sheet P4_TXRXD_N
P4_TXRXD_P: J3.8(TRD4+) ; off-sheet P4_TXRXD_P
P5_LED0: J1.31(1_LED3_CATHODE) ; off-sheet P5_LED0
P5_LED1: J1.34(1_LED4_2) ; off-sheet P5_LED1
P5_TXRXA_N: J1.13(1_TRD1-) ; off-sheet P5_TXRXA_N
P5_TXRXA_P: J1.6(1_TRD1+) ; off-sheet P5_TXRXA_P
P5_TXRXB_N: J1.5(1_TRD2-) ; off-sheet P5_TXRXB_N
P5_TXRXB_P: J1.11(1_TRD2+) ; off-sheet P5_TXRXB_P
P5_TXRXC_N: J1.10(1_TRD3-) ; off-sheet P5_TXRXC_N
P5_TXRXC_P: J1.3(1_TRD3+) ; off-sheet P5_TXRXC_P
P5_TXRXD_N: J1.2(1_TRD4-) ; off-sheet P5_TXRXD_N
P5_TXRXD_P: J1.8(1_TRD4+) ; off-sheet P5_TXRXD_P
NetC26_2: C26.2 J1.4(1_TRCT3) J1.7(1_TRCT1) J1.9(1_TRCT4) J1.12(1_TRCT2)
NetC27_2: C27.2 J2.4(1_TRCT3) J2.7(1_TRCT1) J2.9(1_TRCT4) J2.12(1_TRCT2)
NetC28_2: C28.2 J3.1(TRCT3) J3.6(TRCT2) J3.7(TRCT4) J3.12(TRCT1)
NetC29_2: C29.2 J2.14(2_TRCT1) J2.17(2_TRCT3) J2.22(2_TRCT2) J2.25(2_TRCT4)
NetC31_2: C31.2 J1.14(2_TRCT1) J1.17(2_TRCT3) J1.22(2_TRCT2) J1.25(2_TRCT4)
NetJ3_13: J3.13(YK_1) R53.1
NetJ3_15: J3.15(OK_1) R108.1
NetJ3_17: J3.17(GK_1) R54.1

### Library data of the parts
C26-C29 C31 = CMP-2100-03643-1: Chip Capacitor, 0.1 uF, +/- 10%, 50 V, -55 to 125 degC, 0603 (1608 Metric), RoHS, Tape and Reel; Manufacturer: Murata; Dielectric Material: Ceramic; Voltage Rating: 50V; Capacitance: 100nF; Dielectric: X7R; Insulation Resistance: 10GR
FB3 = CMP-2000-05400-1: Chip Bead for Power Line, 600 Ohm, +/- 25%, 2 A, -55 to 125 degC, 2-Pin SMD (0805), RoHS, Tape and Reel; Manufacturer: TDK; Maximum DC Current: 2A; Impedance: 600Ohms; Test Frequency: 100MHz; Case Length: 2mm; Maximum DC Resistance: 100mOhms; Case Height: 0.85mm; Case Width: 1.25mm
J1 J2 = CMP-16034-000001-1: CONN MAGJACK 2PORT 1000 BASE-T; Manufacturer: Bel Fuse; Is Female: yes; Number Of Contacts: 26; Pitch: 2.01mm; Conn Gender: Female; Shielding: false; Conn Orientation: Horizontal
J3 = L829-1J1T-JM: MagJack 2.5GBASE-T ¦ 1X1 ¦ OG/Y LED ¦ -40 to 85C ¦ RoHS; MF: Bel Magnetic Solutions
R53 R54 R108 = CMP-2002-03891-1: Part Number: RK73H1ETTP2200F; Manufacturer: KOA Speer

## Sheet 05-Switch_SFP_CM4_RJ45.SchDoc
size B; SheetNumber: 5; SheetTotal: 13
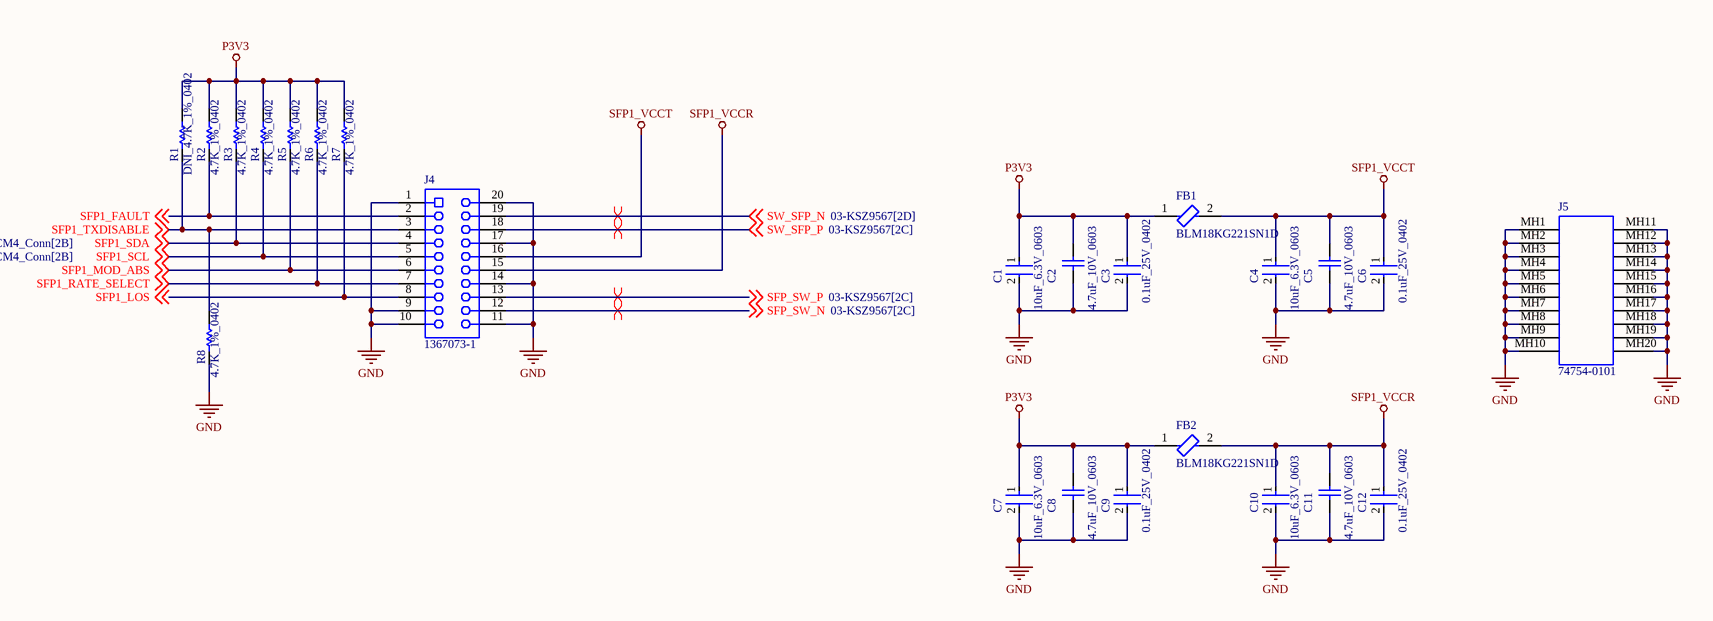
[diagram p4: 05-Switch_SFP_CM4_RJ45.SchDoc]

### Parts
C1  10uF_6.3V_0603  [FP-C0603C106M9PACTU-MFG]
C2  4.7uF_10V_0603  [CAPC1608X87X35NL15T15]
C3  0.1uF_25V_0402  [FP-0402-L_1_0_1-W_0_5_0_1-IPC_C]
C4  10uF_6.3V_0603  [FP-C0603C106M9PACTU-MFG]
C5  4.7uF_10V_0603  [CAPC1608X87X35NL15T15]
C6  0.1uF_25V_0402  [FP-0402-L_1_0_1-W_0_5_0_1-IPC_C]
C7  10uF_6.3V_0603  [FP-C0603C106M9PACTU-MFG]
C8  4.7uF_10V_0603  [CAPC1608X87X35NL15T15]
C9  0.1uF_25V_0402  [FP-0402-L_1_0_1-W_0_5_0_1-IPC_C]
C10  10uF_6.3V_0603  [FP-C0603C106M9PACTU-MFG]
C11  4.7uF_10V_0603  [CAPC1608X87X35NL15T15]
C12  0.1uF_25V_0402  [FP-0402-L_1_0_1-W_0_5_0_1-IPC_C]
FB1  BLM18KG221SN1D  [FP-BLM18-0_15-t0_8-IPC_B]
FB2  BLM18KG221SN1D  [FP-BLM18-0_15-t0_8-IPC_B]
J4  1367073-1  [TECO-1367073-1_V]
J5  74754-0101  [MOLX-74754-0101_V]
R1  DNI_4.7K_1%_0402  [RESC1005X40X25NL10T10]  (no BOM)
R2  4.7K_1%_0402  [RESC1005X40X25NL10T10]
R3  4.7K_1%_0402  [RESC1005X40X25NL10T10]
R4  4.7K_1%_0402  [RESC1005X40X25NL10T10]
R5  4.7K_1%_0402  [RESC1005X40X25NL10T10]
R6  4.7K_1%_0402  [RESC1005X40X25NL10T10]
R7  4.7K_1%_0402  [RESC1005X40X25NL10T10]
R8  4.7K_1%_0402  [RESC1005X40X25NL10T10]

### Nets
GND: C1.2 C2.1 C3.2 C4.2 C5.1 C6.2 C7.2 C8.1 C9.2 C10.2 C11.1 C12.2 J4.1 J4.9 J4.10 J4.11 J4.14 J4.17 J4.20 J5.MH1 J5.MH2 J5.MH3 J5.MH4 J5.MH5 J5.MH6 J5.MH7 J5.MH8 J5.MH9 J5.MH10 J5.MH11 J5.MH12 J5.MH13 J5.MH14 J5.MH15 J5.MH16 J5.MH17 J5.MH18 J5.MH19 J5.MH20 R8.2
P3V3: C1.1 C2.2 C3.1 C7.1 C8.2 C9.1 FB1.1 FB2.1 R1.1 R2.1 R3.1 R4.1 R5.1 R6.1 R7.1
SFP1_VCCR: C10.1 C11.2 C12.1 FB2.2 J4.15
SFP1_VCCT: C4.1 C5.2 C6.1 FB1.2 J4.16
SFP1_FAULT: J4.2 R2.2 ; off-sheet SFP1_FAULT
SFP1_LOS: J4.8 R7.2 ; off-sheet SFP1_LOS
SFP1_MOD_ABS: J4.6 R5.2 ; off-sheet SFP1_MOD_ABS
SFP1_RATE_SELECT: J4.7 R6.2 ; off-sheet SFP1_RATE_SELECT
SFP1_SCL: J4.5 R4.2 ; off-sheet SFP1_SCL
SFP1_SDA: J4.4 R3.2 ; off-sheet SFP1_SDA
SFP1_TXDISABLE: J4.3 R1.2 R8.1 ; off-sheet SFP1_TXDISABLE
SFP_SW_N: J4.12 ; off-sheet SFP_SW_N
SFP_SW_P: J4.13 ; off-sheet SFP_SW_P
SW_SFP_N: J4.19 ; off-sheet SW_SFP_N
SW_SFP_P: J4.18 ; off-sheet SW_SFP_P

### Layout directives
differential pair: SFP_SW_N, SFP_SW_P, SW_SFP_N, SW_SFP_P

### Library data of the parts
C1 C4 C7 C10 = CMP-2006-02285-3: CAP CER 10UF 6.3V X5R 0603; Manufacturer Part Number: C0603C106M9PACTU; Manufacturer: Kemet; Material: Ceramic; Temperature Coefficient: 15%; Tolerance: 20%
C2 C5 C8 C11 = CMP-2006-03238-1: Part Number: C0603C475K8PACTU; Manufacturer: Kemet
C3 C6 C9 C12 = CMP-2008-02519-2: General Purpose Ceramic Capacitor, 0402, 100nF, 10%, X7R, 15%, 25V
FB1 FB2 = CMP-0686-00556-7: Chip Ferrite Bead, 0603, 220Ω @ 100MHz, 0.05Ω, 25%, 2.2A; DC Resistance (DCR): 50mR; Number of Circuits: 1; Impedance: 220R
J4 = CMP-2000-05488-1: Female Connector, Pitch 0.8 mm, 2 x 10 Position, Height 5.4 mm, -55 to 85 degC, RoHS, Tape and Reel; Manufacturer: TE Connectivity; Product Training Modules: HighSpeedPluggableI/OSolutions; 3D Model: 1367073-1.pdf; Connector Type: SFP; Other Names: A97430DKR; Mating Products: 516-2084-ND / -TXRXOPTICALSFF1.25GBDISCSI; Dynamic Catalog: SFPConnectors; Featured Product: HighSpeedPluggableI-OSolutions; Connector Style: Receptacle; Associated Product: A103997CT-ND / -CONNSFPCAGESINGLEW/OPIPE / A103997TR-ND / -CONNSFPCAGESINGLEW/OPIPE / 1367645-3-ND / -CONNCAGE&HEATSINKSGLPORTTIN / 1367645-2-ND / -CONNCAGE&HEATSINKSGLPORTTIN / 1888424-1-ND / -CONNCAGE1X2SFPENHANCEDEMI / 1367643-1-ND / -CONNCAGESNGLPORTDBLSIDETIN / 1489962-1-ND / -CONNSFPCAGESINGLEW/OPIPE / 1367645-1-ND / -CONNCAGE&HEATSINKSGLPORTTIN / A99375-ND / -CONNSFPCAGE1X4PIN-IN-PASTE / A97412CT-ND / -CONNSFPLOWERCAGEPCB / More...; Number of Positions: 20
J5 = CMP-1704-00003-3: SFP+ Cage, Single Port, Height 10.85 mm, Tail Height 3.05 mm, -40 to 85 degC, RoHS, Tray
R1-R8 = CMP-2002-05217-1: as R9 on sheet 01-CM4_Conn

## Sheet 06-CM4_USB_HDMI_SDCard.SchDoc
size B; SheetNumber: 6; SheetTotal: 13
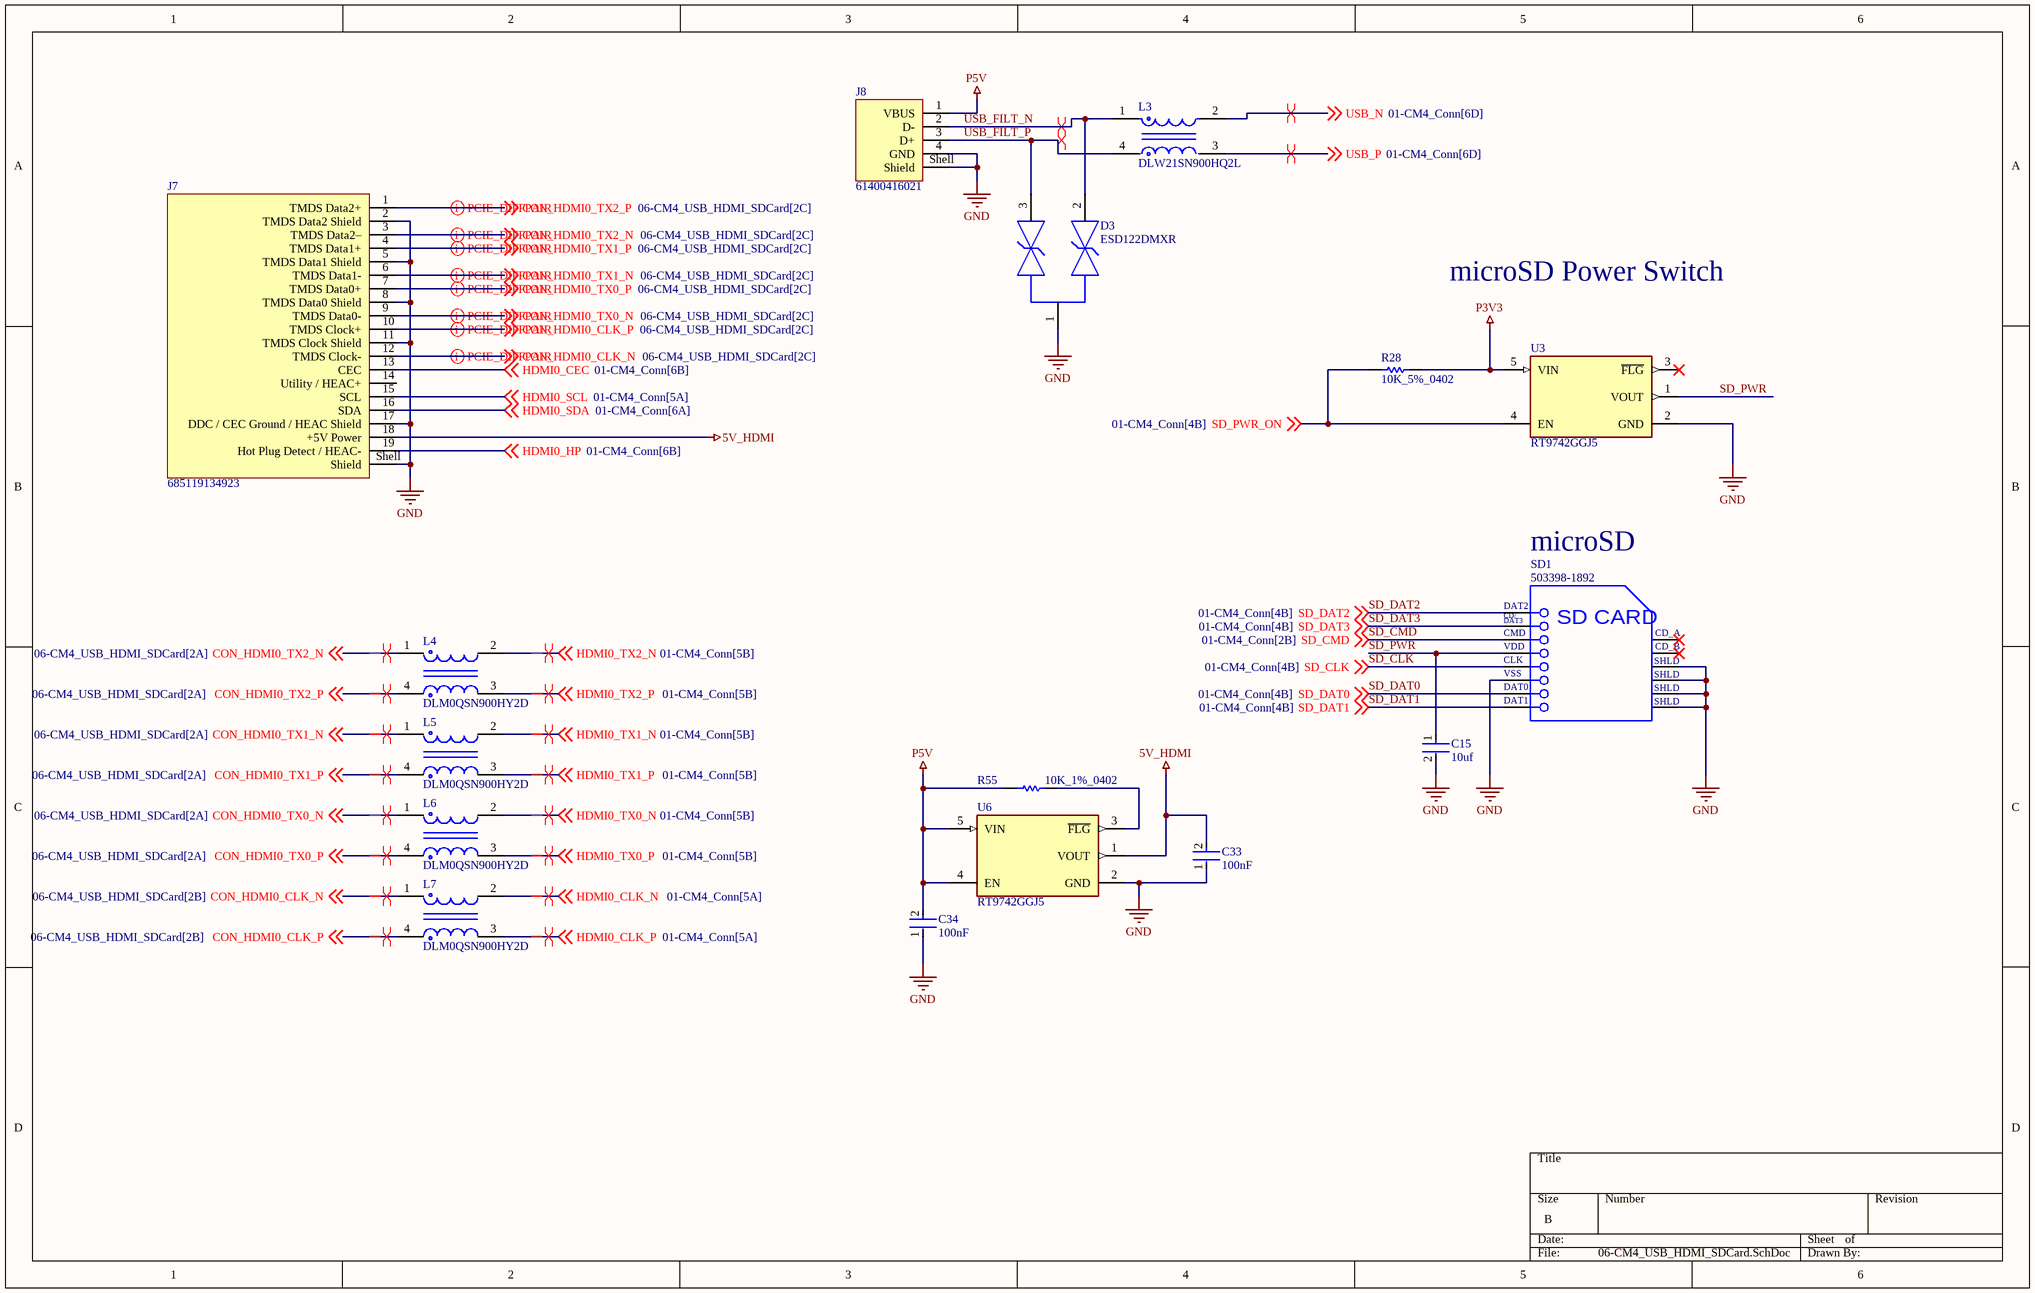
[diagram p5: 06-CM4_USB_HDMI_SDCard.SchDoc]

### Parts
C15  10uf  [FP-GRM188-0_2-IPC_C]
C33  100nF  [FP-GRM15-MFG]
C34  100nF  [FP-GRM15-MFG]
D3  ESD122DMXR  [FP-DMX0003A-MFG]
J7  685119134923  [685119134923]
J8  61400416021  [61400416021]
L3  DLW21SN900HQ2L  [FP-DLW21S-MFG]
L4  DLM0QSN900HY2D  [FP-DLM0Q-MFG]
L5  DLM0QSN900HY2D  [FP-DLM0Q-MFG]
L6  DLM0QSN900HY2D  [FP-DLM0Q-MFG]
L7  DLM0QSN900HY2D  [FP-DLM0Q-MFG]
R28  10K_5%_0402  [RESC1005X40X25ML05T05]
R55  10K_1%_0402  [RESC1005X40X25NL10T10]
SD1  503398-1892  [MOLX-503398-1892_V]
U3  RT9742GGJ5  [FP-RT9742GGJ5-IPC_C]
U6  RT9742GGJ5  [FP-RT9742GGJ5-IPC_C]

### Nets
5V_HDMI: C33.2 J7.18(+5V_Power) U6.1(VOUT)
GND: C15.2 C33.1 C34.1 D3.1(GND) J7.2(TMDS_Data2_Shield) J7.5(TMDS_Data1_Shield) J7.8(TMDS_Data0_Shield) J7.11(TMDS_Clock_Shield) J7.17(DDC_/_CEC_Ground_/_HEAC_Shield) J7.Shell(Shield) J8.4(GND) J8.Shell(Shield) SD1.6(VSS) SD1.11(SHLD) SD1.12(SHLD) SD1.13(SHLD) SD1.14(SHLD) U3.2(GND) U6.2(GND)
P3V3: R28.2 U3.5(VIN)
P5V: C34.2 J8.1(VBUS) R55.1 U6.4(EN) U6.5(VIN)
CON_HDMI0_CLK_N: J7.12(TMDS_Clock-) L7.1 ; off-sheet CON_HDMI0_CLK_N
CON_HDMI0_CLK_P: J7.10(TMDS_Clock+) L7.4 ; off-sheet CON_HDMI0_CLK_P
CON_HDMI0_TX0_N: J7.9(TMDS_Data0-) L6.1 ; off-sheet CON_HDMI0_TX0_N
CON_HDMI0_TX0_P: J7.7(TMDS_Data0+) L6.4 ; off-sheet CON_HDMI0_TX0_P
CON_HDMI0_TX1_N: J7.6(TMDS_Data1-) L5.1 ; off-sheet CON_HDMI0_TX1_N
CON_HDMI0_TX1_P: J7.4(TMDS_Data1+) L5.4 ; off-sheet CON_HDMI0_TX1_P
CON_HDMI0_TX2_N: J7.3(TMDS_Data2–) L4.1 ; off-sheet CON_HDMI0_TX2_N
CON_HDMI0_TX2_P: J7.1(TMDS_Data2+) L4.4 ; off-sheet CON_HDMI0_TX2_P
HDMI0_CEC: J7.13(CEC) ; off-sheet HDMI0_CEC
HDMI0_CLK_N: L7.2 ; off-sheet HDMI0_CLK_N
HDMI0_CLK_P: L7.3 ; off-sheet HDMI0_CLK_P
HDMI0_HP: J7.19(Hot_Plug_Detect_/_HEAC-) ; off-sheet HDMI0_HP
HDMI0_SCL: J7.15(SCL) ; off-sheet HDMI0_SCL
HDMI0_SDA: J7.16(SDA) ; off-sheet HDMI0_SDA
HDMI0_TX0_N: L6.2 ; off-sheet HDMI0_TX0_N
HDMI0_TX0_P: L6.3 ; off-sheet HDMI0_TX0_P
HDMI0_TX1_N: L5.2 ; off-sheet HDMI0_TX1_N
HDMI0_TX1_P: L5.3 ; off-sheet HDMI0_TX1_P
HDMI0_TX2_N: L4.2 ; off-sheet HDMI0_TX2_N
HDMI0_TX2_P: L4.3 ; off-sheet HDMI0_TX2_P
SD_CLK: SD1.5(CLK) ; off-sheet SD_CLK
SD_CMD: SD1.3(CMD) ; off-sheet SD_CMD
SD_DAT0: SD1.7(DAT0) ; off-sheet SD_DAT0
SD_DAT1: SD1.8(DAT1) ; off-sheet SD_DAT1
SD_DAT2: SD1.1(DAT2) ; off-sheet SD_DAT2
SD_DAT3: SD1.2(CD/DAT3) ; off-sheet SD_DAT3
SD_PWR: C15.1 SD1.4(VDD) U3.1(VOUT)
SD_PWR_ON: R28.1 U3.4(EN) ; off-sheet SD_PWR_ON
USB_FILT_N: D3.2(IO1) J8.2(D-) L3.1
USB_FILT_P: D3.3(IO2) J8.3(D+) L3.4
USB_N: L3.2 ; off-sheet USB_N
USB_P: L3.3 ; off-sheet USB_P
NetR55_2: R55.2 U6.3(~{FLG})

Not connected (* = marked no-connect by the designer): J7 14(Utility_/_HEAC+); SD1 9(CD_A)* 10(CD_B)*; U3 3(~{FLG})*

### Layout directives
differential pair; differential pair class HDMI: CON_HDMI0_CLK_N, CON_HDMI0_CLK_P, CON_HDMI0_TX0_N, CON_HDMI0_TX0_P, CON_HDMI0_TX1_N, CON_HDMI0_TX1_P, CON_HDMI0_TX2_N, CON_HDMI0_TX2_P
differential pair: CON_HDMI0_CLK_N, CON_HDMI0_CLK_P, CON_HDMI0_TX0_N, CON_HDMI0_TX0_P, CON_HDMI0_TX1_N, CON_HDMI0_TX1_P, CON_HDMI0_TX2_N, CON_HDMI0_TX2_P, HDMI0_CLK_N, HDMI0_CLK_P, HDMI0_TX0_N, HDMI0_TX0_P, HDMI0_TX1_N, HDMI0_TX1_P, HDMI0_TX2_N, HDMI0_TX2_P, USB_FILT_N, USB_FILT_P, USB_N, USB_P

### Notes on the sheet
- microSD Power Switch
- microSD

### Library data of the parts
C15 = CMP-06035-045466-1: Chip Multilayer Ceramic Capacitors for General Purpose, 0603, 10uF, X5R, 15%, 20%, 35V
C33 C34 = CMP-2100-03641-2: CAP CER 0.1UF 16V X7R 0402; Manufacturer Part Number: GRM155R71C104KA88D; Manufacturer: Murata; Standoff Height: 0mm; Tolerance: 10%; Voltage Rating: 16Vdc; Material: Ceramic; Capacitance: 0.10μF; Value: 0.10μF
D3 = CMP-04989-000013-1: TVS DIODE 3.6V 8.4V 3X2SON; Peak Pulse Power: 20W; Min Breakdown Voltage: 5.1V; Average Rectified Current: 10A; Element Configuration: Common Cathode; Number of Channels: 2; Max Reverse Voltage (DC): 100V; Interface: USB; Power Line Protection: No; Peak Pulse Current: 2.5A
J7 = CMP-1502-00169-3: NexarPartId: 18818285; Connector Type: HDMI; Contact Resistance: 30mΩ; Current Rating: 500mA; Gender: Receptacle; Insulation Resistance: 10MΩ; Number of Contacts: 19; Body Material: Plastic; Voltage Rating: 40V
J8 = CMP-1502-03227-2: NexarPartId: 21041530; Contact Resistance: 20mΩ; Gender: Receptacle; Voltage Rating (DC): 30V; Current Rating: 1.5A; Connector Type: USB; Insulation Resistance: 1GΩ; USB Standard: USB 2.0; Number of Contacts: 4; Number of Ports: 1
L3 = CMP-2000-06163-2: Common Mode Choke, 0805, 90Ω @ 100MHz, 0.41Ω, 25%, 280mA; Impedance: 90R; Shielding: Unshielded; DC Resistance (DCR): 410mR; Number of Lines: 2
L4-L7 = CMP-06045-000424-1: Chip Common Mode Choke Coil Monolithic 025020 50mA 90Ohm @ 100MHz; Impedance: 90R
R28 = CMP-2002-00433-1: Part Number: ERJ-2GEJ103X; Manufacturer: Panasonic
R55 = CMP-2002-04694-1: as R52 on sheet 01-CM4_Conn
SD1 = CMP-2000-05621-1: Micro SD Connector, Pitch 1.1 mm, 8 Position, Height 1.4 mm, -25 to 85 degC, RoHS, Tape and Reel; Manufacturer: Molex; Voltage Rating: 10VAC/DC; Current Rating: 500mA
U3 U6 = CMP-79883-000001-1: IC PWR SWTCH N-CHAN 1:1 TSOT23-5; Interface: On/Off; Fault Protection: Over Temperature; Max Output Current: 1A; Number of Outputs: 1; Output Configuration: High Side; On-State Resistance: 70mR

## Sheet 07-KSZ9031_1G_BASET_XCVR.SchDoc
size C; SheetNumber: 7; SheetTotal: 13
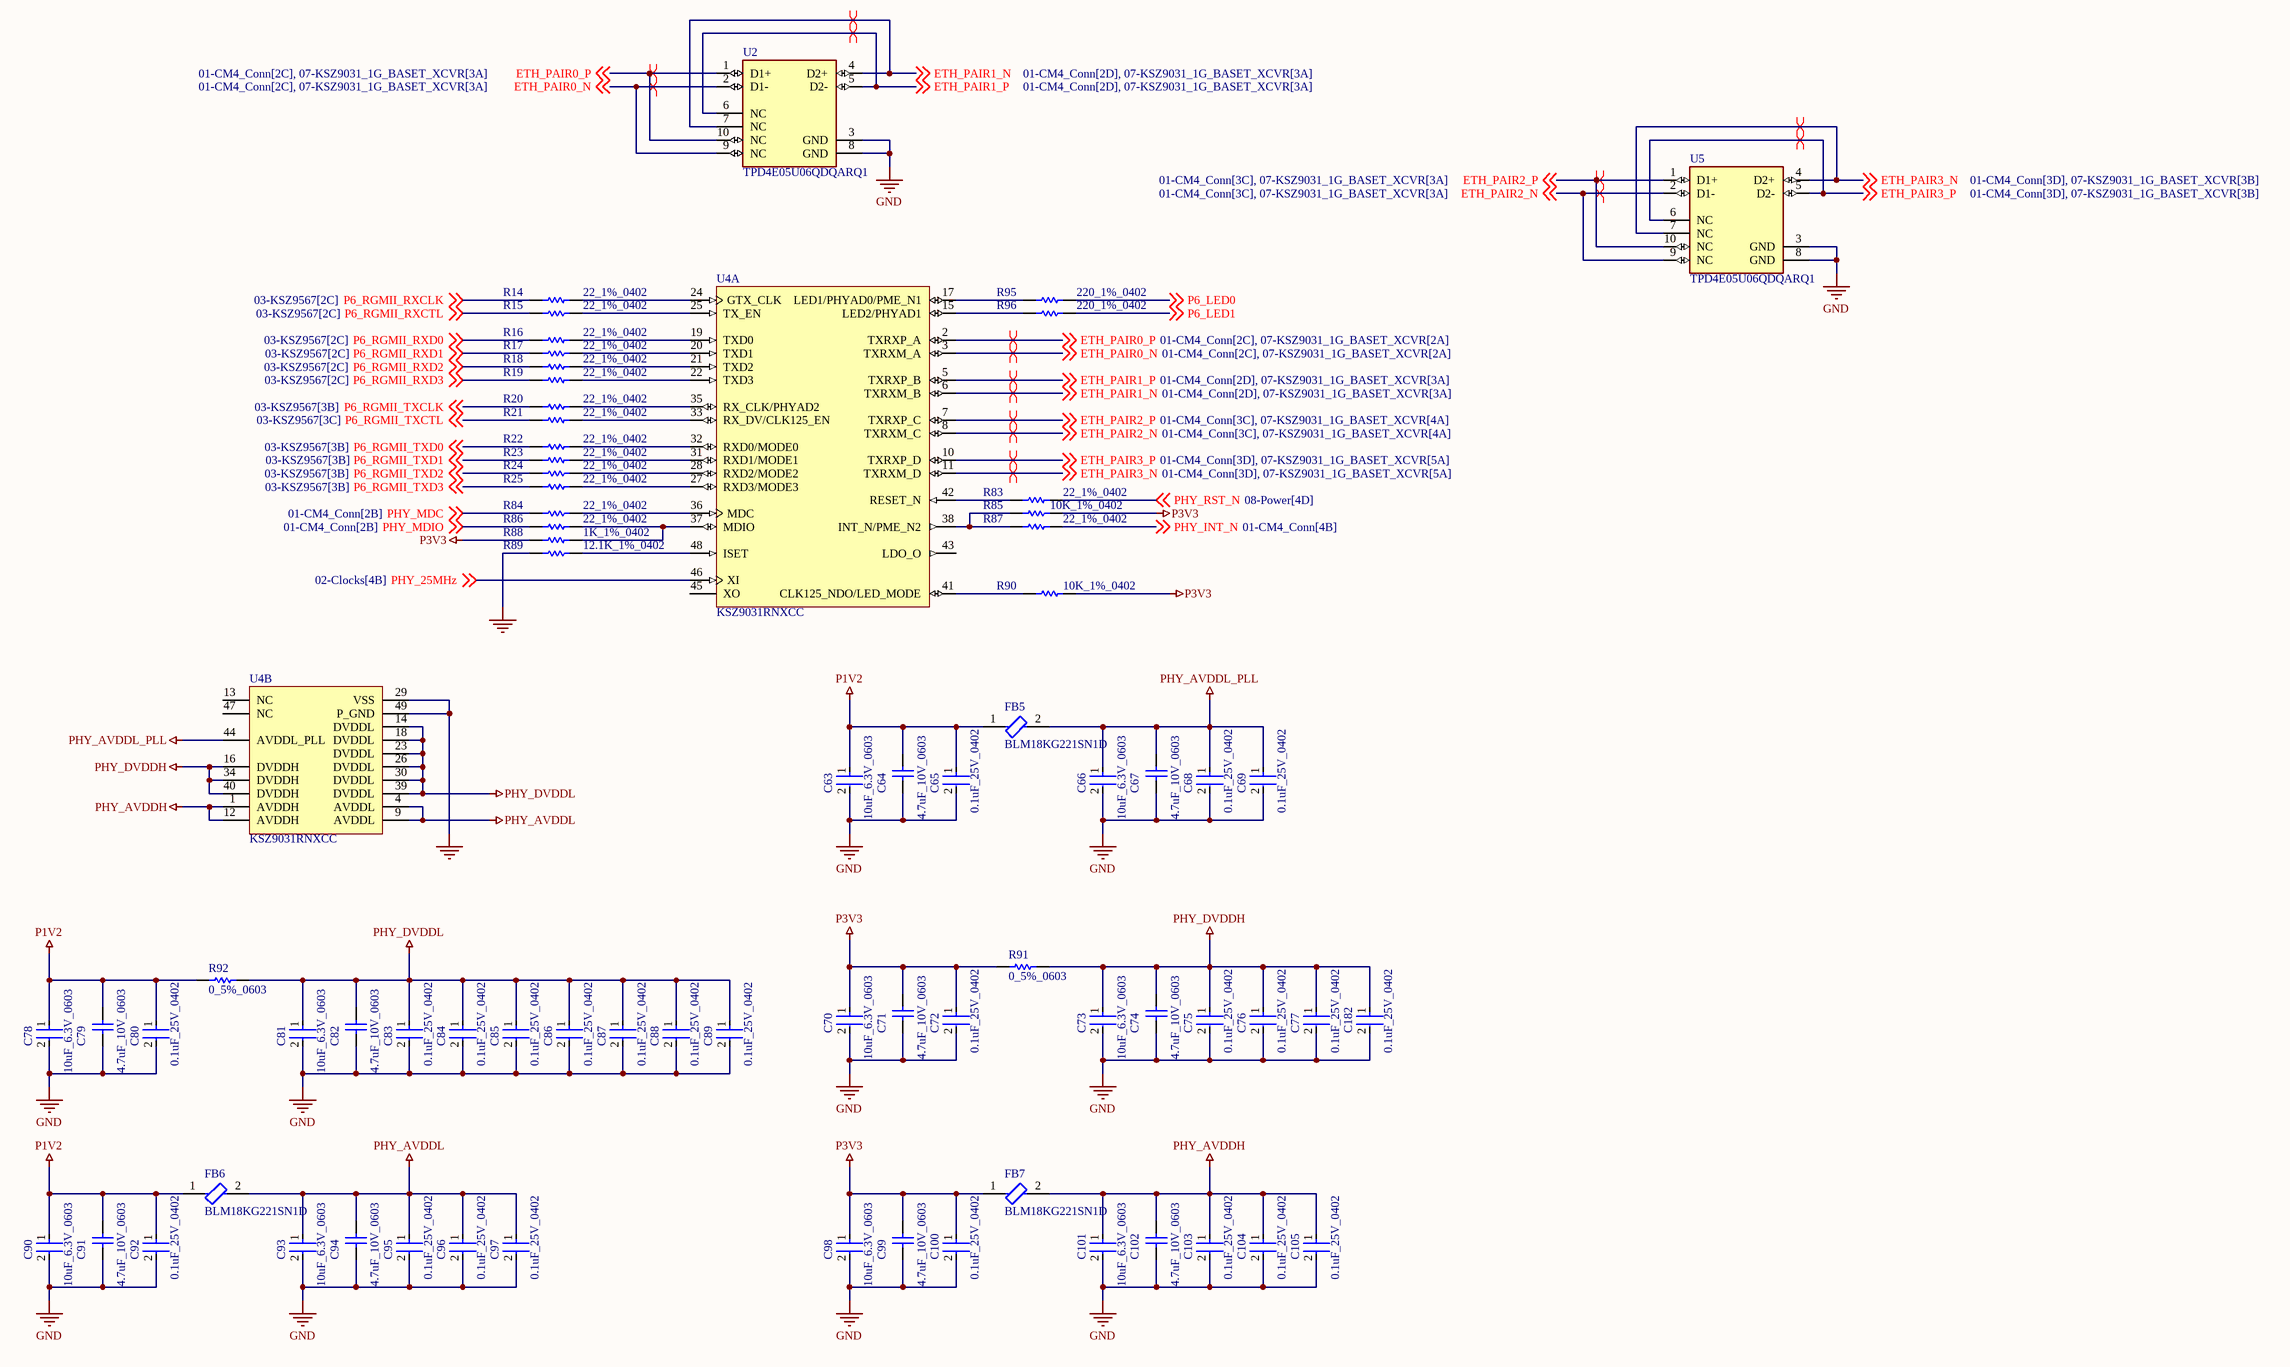
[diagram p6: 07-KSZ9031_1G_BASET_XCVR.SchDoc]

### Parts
C63  10uF_6.3V_0603  [FP-C0603C106M9PACTU-MFG]
C64  4.7uF_10V_0603  [CAPC1608X87X35NL15T15]
C65  0.1uF_25V_0402  [FP-0402-L_1_0_1-W_0_5_0_1-IPC_C]
C66  10uF_6.3V_0603  [FP-C0603C106M9PACTU-MFG]
C67  4.7uF_10V_0603  [CAPC1608X87X35NL15T15]
C68  0.1uF_25V_0402  [FP-0402-L_1_0_1-W_0_5_0_1-IPC_C]
C69  0.1uF_25V_0402  [FP-0402-L_1_0_1-W_0_5_0_1-IPC_C]
C70  10uF_6.3V_0603  [FP-C0603C106M9PACTU-MFG]
C71  4.7uF_10V_0603  [CAPC1608X87X35NL15T15]
C72  0.1uF_25V_0402  [FP-0402-L_1_0_1-W_0_5_0_1-IPC_C]
C73  10uF_6.3V_0603  [FP-C0603C106M9PACTU-MFG]
C74  4.7uF_10V_0603  [CAPC1608X87X35NL15T15]
C75  0.1uF_25V_0402  [FP-0402-L_1_0_1-W_0_5_0_1-IPC_C]
C76  0.1uF_25V_0402  [FP-0402-L_1_0_1-W_0_5_0_1-IPC_C]
C77  0.1uF_25V_0402  [FP-0402-L_1_0_1-W_0_5_0_1-IPC_C]
C78  10uF_6.3V_0603  [FP-C0603C106M9PACTU-MFG]
C79  4.7uF_10V_0603  [CAPC1608X87X35NL15T15]
C80  0.1uF_25V_0402  [FP-0402-L_1_0_1-W_0_5_0_1-IPC_C]
C81  10uF_6.3V_0603  [FP-C0603C106M9PACTU-MFG]
C82  4.7uF_10V_0603  [CAPC1608X87X35NL15T15]
C83  0.1uF_25V_0402  [FP-0402-L_1_0_1-W_0_5_0_1-IPC_C]
C84  0.1uF_25V_0402  [FP-0402-L_1_0_1-W_0_5_0_1-IPC_C]
C85  0.1uF_25V_0402  [FP-0402-L_1_0_1-W_0_5_0_1-IPC_C]
C86  0.1uF_25V_0402  [FP-0402-L_1_0_1-W_0_5_0_1-IPC_C]
C87  0.1uF_25V_0402  [FP-0402-L_1_0_1-W_0_5_0_1-IPC_C]
C88  0.1uF_25V_0402  [FP-0402-L_1_0_1-W_0_5_0_1-IPC_C]
C89  0.1uF_25V_0402  [FP-0402-L_1_0_1-W_0_5_0_1-IPC_C]
C90  10uF_6.3V_0603  [FP-C0603C106M9PACTU-MFG]
C91  4.7uF_10V_0603  [CAPC1608X87X35NL15T15]
C92  0.1uF_25V_0402  [FP-0402-L_1_0_1-W_0_5_0_1-IPC_C]
C93  10uF_6.3V_0603  [FP-C0603C106M9PACTU-MFG]
C94  4.7uF_10V_0603  [CAPC1608X87X35NL15T15]
C95  0.1uF_25V_0402  [FP-0402-L_1_0_1-W_0_5_0_1-IPC_C]
C96  0.1uF_25V_0402  [FP-0402-L_1_0_1-W_0_5_0_1-IPC_C]
C97  0.1uF_25V_0402  [FP-0402-L_1_0_1-W_0_5_0_1-IPC_C]
C98  10uF_6.3V_0603  [FP-C0603C106M9PACTU-MFG]
C99  4.7uF_10V_0603  [CAPC1608X87X35NL15T15]
C100  0.1uF_25V_0402  [FP-0402-L_1_0_1-W_0_5_0_1-IPC_C]
C101  10uF_6.3V_0603  [FP-C0603C106M9PACTU-MFG]
C102  4.7uF_10V_0603  [CAPC1608X87X35NL15T15]
C103  0.1uF_25V_0402  [FP-0402-L_1_0_1-W_0_5_0_1-IPC_C]
C104  0.1uF_25V_0402  [FP-0402-L_1_0_1-W_0_5_0_1-IPC_C]
C105  0.1uF_25V_0402  [FP-0402-L_1_0_1-W_0_5_0_1-IPC_C]
C182  0.1uF_25V_0402  [FP-0402-L_1_0_1-W_0_5_0_1-IPC_C]
FB5  BLM18KG221SN1D  [FP-BLM18-0_15-t0_8-IPC_B]
FB6  BLM18KG221SN1D  [FP-BLM18-0_15-t0_8-IPC_B]
FB7  BLM18KG221SN1D  [FP-BLM18-0_15-t0_8-IPC_B]
R14  22_1%_0402  [RESC1005X40X25ML05T10]
R15  22_1%_0402  [RESC1005X40X25ML05T10]
R16  22_1%_0402  [RESC1005X40X25ML05T10]
R17  22_1%_0402  [RESC1005X40X25ML05T10]
R18  22_1%_0402  [RESC1005X40X25ML05T10]
R19  22_1%_0402  [RESC1005X40X25ML05T10]
R20  22_1%_0402  [RESC1005X40X25ML05T10]
R21  22_1%_0402  [RESC1005X40X25ML05T10]
R22  22_1%_0402  [RESC1005X40X25ML05T10]
R23  22_1%_0402  [RESC1005X40X25ML05T10]
R24  22_1%_0402  [RESC1005X40X25ML05T10]
R25  22_1%_0402  [RESC1005X40X25ML05T10]
R83  22_1%_0402  [RESC1005X40X25ML05T10]
R84  22_1%_0402  [RESC1005X40X25ML05T10]
R85  10K_1%_0402  [RESC1005X40X25NL10T10]
R86  22_1%_0402  [RESC1005X40X25ML05T10]
R87  22_1%_0402  [RESC1005X40X25ML05T10]
R88  1K_1%_0402  [RESC1005X40X25ML05T10]
R89  12.1K_1%_0402  [RESC1005X40X25NL10T10]
R90  10K_1%_0402  [RESC1005X40X25NL10T10]
R91  0_5%_0603  [RESC1608X55X25ML10T15]
R92  0_5%_0603  [RESC1608X55X25ML10T15]
R95  220_1%_0402  [RESC1005X40X25NL05T10]
R96  220_1%_0402  [RESC1005X40X25NL05T10]
U2  TPD4E05U06QDQARQ1  [FP-DQA0010A-MFG]
U4  KSZ9031RNXCC  [MICL-QFN-48_V]  (parts A,B of 2)
U5  TPD4E05U06QDQARQ1  [FP-DQA0010A-MFG]

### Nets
GND: C63.2 C64.1 C65.2 C66.2 C67.1 C68.2 C69.2 C70.2 C71.1 C72.2 C73.2 C74.1 C75.2 C76.2 C77.2 C78.2 C79.1 C80.2 C81.2 C82.1 C83.2 C84.2 C85.2 C86.2 C87.2 C88.2 C89.2 C90.2 C91.1 C92.2 C93.2 C94.1 C95.2 C96.2 C97.2 C98.2 C99.1 C100.2 C101.2 C102.1 C103.2 C104.2 C105.2 C182.2 R89.1 U2.3(GND) U2.8(GND) U4.29(VSS) U4.49(P_GND) U5.3(GND) U5.8(GND)
P1V2: C63.1 C64.2 C65.1 C78.1 C79.2 C80.1 C90.1 C91.2 C92.1 FB5.1 FB6.1 R92.1
P3V3: C70.1 C71.2 C72.1 C98.1 C99.2 C100.1 FB7.1 R85.2 R88.1 R90.2 R91.1
PHY_AVDDH: C101.1 C102.2 C103.1 C104.1 C105.1 FB7.2 U4.1(AVDDH) U4.12(AVDDH)
PHY_AVDDL: C93.1 C94.2 C95.1 C96.1 C97.1 FB6.2 U4.4(AVDDL) U4.9(AVDDL)
PHY_AVDDL_PLL: C66.1 C67.2 C68.1 C69.1 FB5.2 U4.44(AVDDL_PLL)
PHY_DVDDH: C73.1 C74.2 C75.1 C76.1 C77.1 C182.1 R91.2 U4.16(DVDDH) U4.34(DVDDH) U4.40(DVDDH)
PHY_DVDDL: C81.1 C82.2 C83.1 C84.1 C85.1 C86.1 C87.1 C88.1 C89.1 R92.2 U4.14(DVDDL) U4.18(DVDDL) U4.23(DVDDL) U4.26(DVDDL) U4.30(DVDDL) U4.39(DVDDL)
ETH_PAIR0_N: U2.2(D1-) U2.9(NC) U4.3(TXRXM_A) ; off-sheet ETH_PAIR0_N
ETH_PAIR0_P: U2.1(D1+) U2.10(NC) U4.2(TXRXP_A) ; off-sheet ETH_PAIR0_P
ETH_PAIR1_N: U2.4(D2+) U2.7(NC) U4.6(TXRXM_B) ; off-sheet ETH_PAIR1_N
ETH_PAIR1_P: U2.5(D2-) U2.6(NC) U4.5(TXRXP_B) ; off-sheet ETH_PAIR1_P
ETH_PAIR2_N: U4.8(TXRXM_C) U5.2(D1-) U5.9(NC) ; off-sheet ETH_PAIR2_N
ETH_PAIR2_P: U4.7(TXRXP_C) U5.1(D1+) U5.10(NC) ; off-sheet ETH_PAIR2_P
ETH_PAIR3_N: U4.11(TXRXM_D) U5.4(D2+) U5.7(NC) ; off-sheet ETH_PAIR3_N
ETH_PAIR3_P: U4.10(TXRXP_D) U5.5(D2-) U5.6(NC) ; off-sheet ETH_PAIR3_P
P6_LED0: R95.2 ; off-sheet P6_LED0
P6_LED1: R96.2 ; off-sheet P6_LED1
P6_RGMII_RXCLK: R14.1 ; off-sheet P6_RGMII_RXCLK
P6_RGMII_RXCTL: R15.1 ; off-sheet P6_RGMII_RXCTL
P6_RGMII_RXD0: R16.1 ; off-sheet P6_RGMII_RXD0
P6_RGMII_RXD1: R17.1 ; off-sheet P6_RGMII_RXD1
P6_RGMII_RXD2: R18.1 ; off-sheet P6_RGMII_RXD2
P6_RGMII_RXD3: R19.1 ; off-sheet P6_RGMII_RXD3
P6_RGMII_TXCLK: R20.1 ; off-sheet P6_RGMII_TXCLK
P6_RGMII_TXCTL: R21.1 ; off-sheet P6_RGMII_TXCTL
P6_RGMII_TXD0: R22.1 ; off-sheet P6_RGMII_TXD0
P6_RGMII_TXD1: R23.1 ; off-sheet P6_RGMII_TXD1
P6_RGMII_TXD2: R24.1 ; off-sheet P6_RGMII_TXD2
P6_RGMII_TXD3: R25.1 ; off-sheet P6_RGMII_TXD3
PHY_25MHz: U4.46(XI) ; off-sheet PHY_25MHz
PHY_INT_N: R87.2 ; off-sheet PHY_INT_N
PHY_MDC: R84.1 ; off-sheet PHY_MDC
PHY_MDIO: R86.1 ; off-sheet PHY_MDIO
PHY_RST_N: R83.2 ; off-sheet PHY_RST_N
NetR14_2: R14.2 U4.24(GTX_CLK)
NetR15_2: R15.2 U4.25(TX_EN)
NetR16_2: R16.2 U4.19(TXD0)
NetR17_2: R17.2 U4.20(TXD1)
NetR18_2: R18.2 U4.21(TXD2)
NetR19_2: R19.2 U4.22(TXD3)
NetR20_2: R20.2 U4.35(RX_CLK/PHYAD2)
NetR21_2: R21.2 U4.33(RX_DV/CLK125_EN)
NetR22_2: R22.2 U4.32(RXD0/MODE0)
NetR23_2: R23.2 U4.31(RXD1/MODE1)
NetR24_2: R24.2 U4.28(RXD2/MODE2)
NetR25_2: R25.2 U4.27(RXD3/MODE3)
NetR83_1: R83.1 U4.42(RESET_N)
NetR84_2: R84.2 U4.36(MDC)
NetR85_1: R85.1 R87.1 U4.38(INT_N/PME_N2)
NetR86_2: R86.2 R88.2 U4.37(MDIO)
NetR89_2: R89.2 U4.48(ISET)
NetR90_1: R90.1 U4.41(CLK125_NDO/LED_MODE)
NetR95_1: R95.1 U4.17(LED1/PHYAD0/PME_N1)
NetR96_1: R96.1 U4.15(LED2/PHYAD1)

Not connected (* = marked no-connect by the designer): U4 13(NC) 43(LDO_O) 45(XO) 47(NC)

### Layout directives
differential pair: ETH_PAIR0_N, ETH_PAIR0_P, ETH_PAIR1_N, ETH_PAIR1_P, ETH_PAIR2_N, ETH_PAIR2_P, ETH_PAIR3_N, ETH_PAIR3_P

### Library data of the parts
C63 C66 C70 C73 C78 C81 C90 C93 C98 C101 = CMP-2006-02285-3: as C1 on sheet 05-Switch_SFP_CM4_RJ45
C64 C67 C71 C74 C79 C82 C91 C94 C99 C102 = CMP-2006-03238-1: as C2 on sheet 05-Switch_SFP_CM4_RJ45
C65 C68 C69 C72 C75-C77 C80 C83-C89 C92 C95-C97 C100 C103-C105 C182 = CMP-2008-02519-2: as C3 on sheet 05-Switch_SFP_CM4_RJ45
FB5-FB7 = CMP-0686-00556-7: as FB1 on sheet 05-Switch_SFP_CM4_RJ45
R14-R25 R83 R84 R86 R87 = CMP-2002-07182-1: Part Number: RC0402FR-1322RL; Manufacturer: Yageo / Phycomp
R85 R90 = CMP-2002-04694-1: as R52 on sheet 01-CM4_Conn
R88 = CMP-2002-06478-1: Manufacturer: Multicomp; Part Number: MCMR04X1001FTL
R89 = CMP-2002-05926-1: Manufacturer: Multicomp; Part Number: MC00625W0402112K1
R91 R92 = CMP-2100-03667-1: Chip Resistor, 0 Ohm, +/- 5%, 0.1 W, -55 to 155 degC, 0603 (1608 Metric), RoHS, Tape and Reel; Manufacturer: Yageo; Temperature Coefficient: 200ppm/degreesC; Voltage Rating: 50V; Power Rating: 100mW; Resistance: 0mOhm
R95 R96 = CMP-2002-07959-1: as R31 on sheet 03-KSZ9567
U2 U5 = CMP-04985-000004-1: TVS DIODE 5.5V 14V 10USON; Manufacturer: Texas Instruments; Direction: Unidirectional; Standoff Height: 0mm; Capacitance: 0.5pF; Number Of Channels: 4; Breakdown Voltage: 6.4V; Peak Pulse Power: 2.5W; Automotive Grade: Grade 1; Value: 0.5pF; Interface: USB,Ethernet,LVDS,Other; Peak Pulse Current: 2.5A
U4 = CMP-1337-00003-2: Gigabit Ethernet Transceiver with RGMII Support, 1.14 to 1.26 V, 0 to 70 degC, 48-Pin QFN, RoHS; Manufacturer: Micrel; Output Tri-State Leakage: 10 uA Max.; ILED: 8 mA Typ.; Receivers: 4; VSET@R(ISET): 12.1 KOhm=1.2 V Typ.

## Sheet 08-Power.SchDoc
size B; SheetNumber: 8; SheetTotal: 11
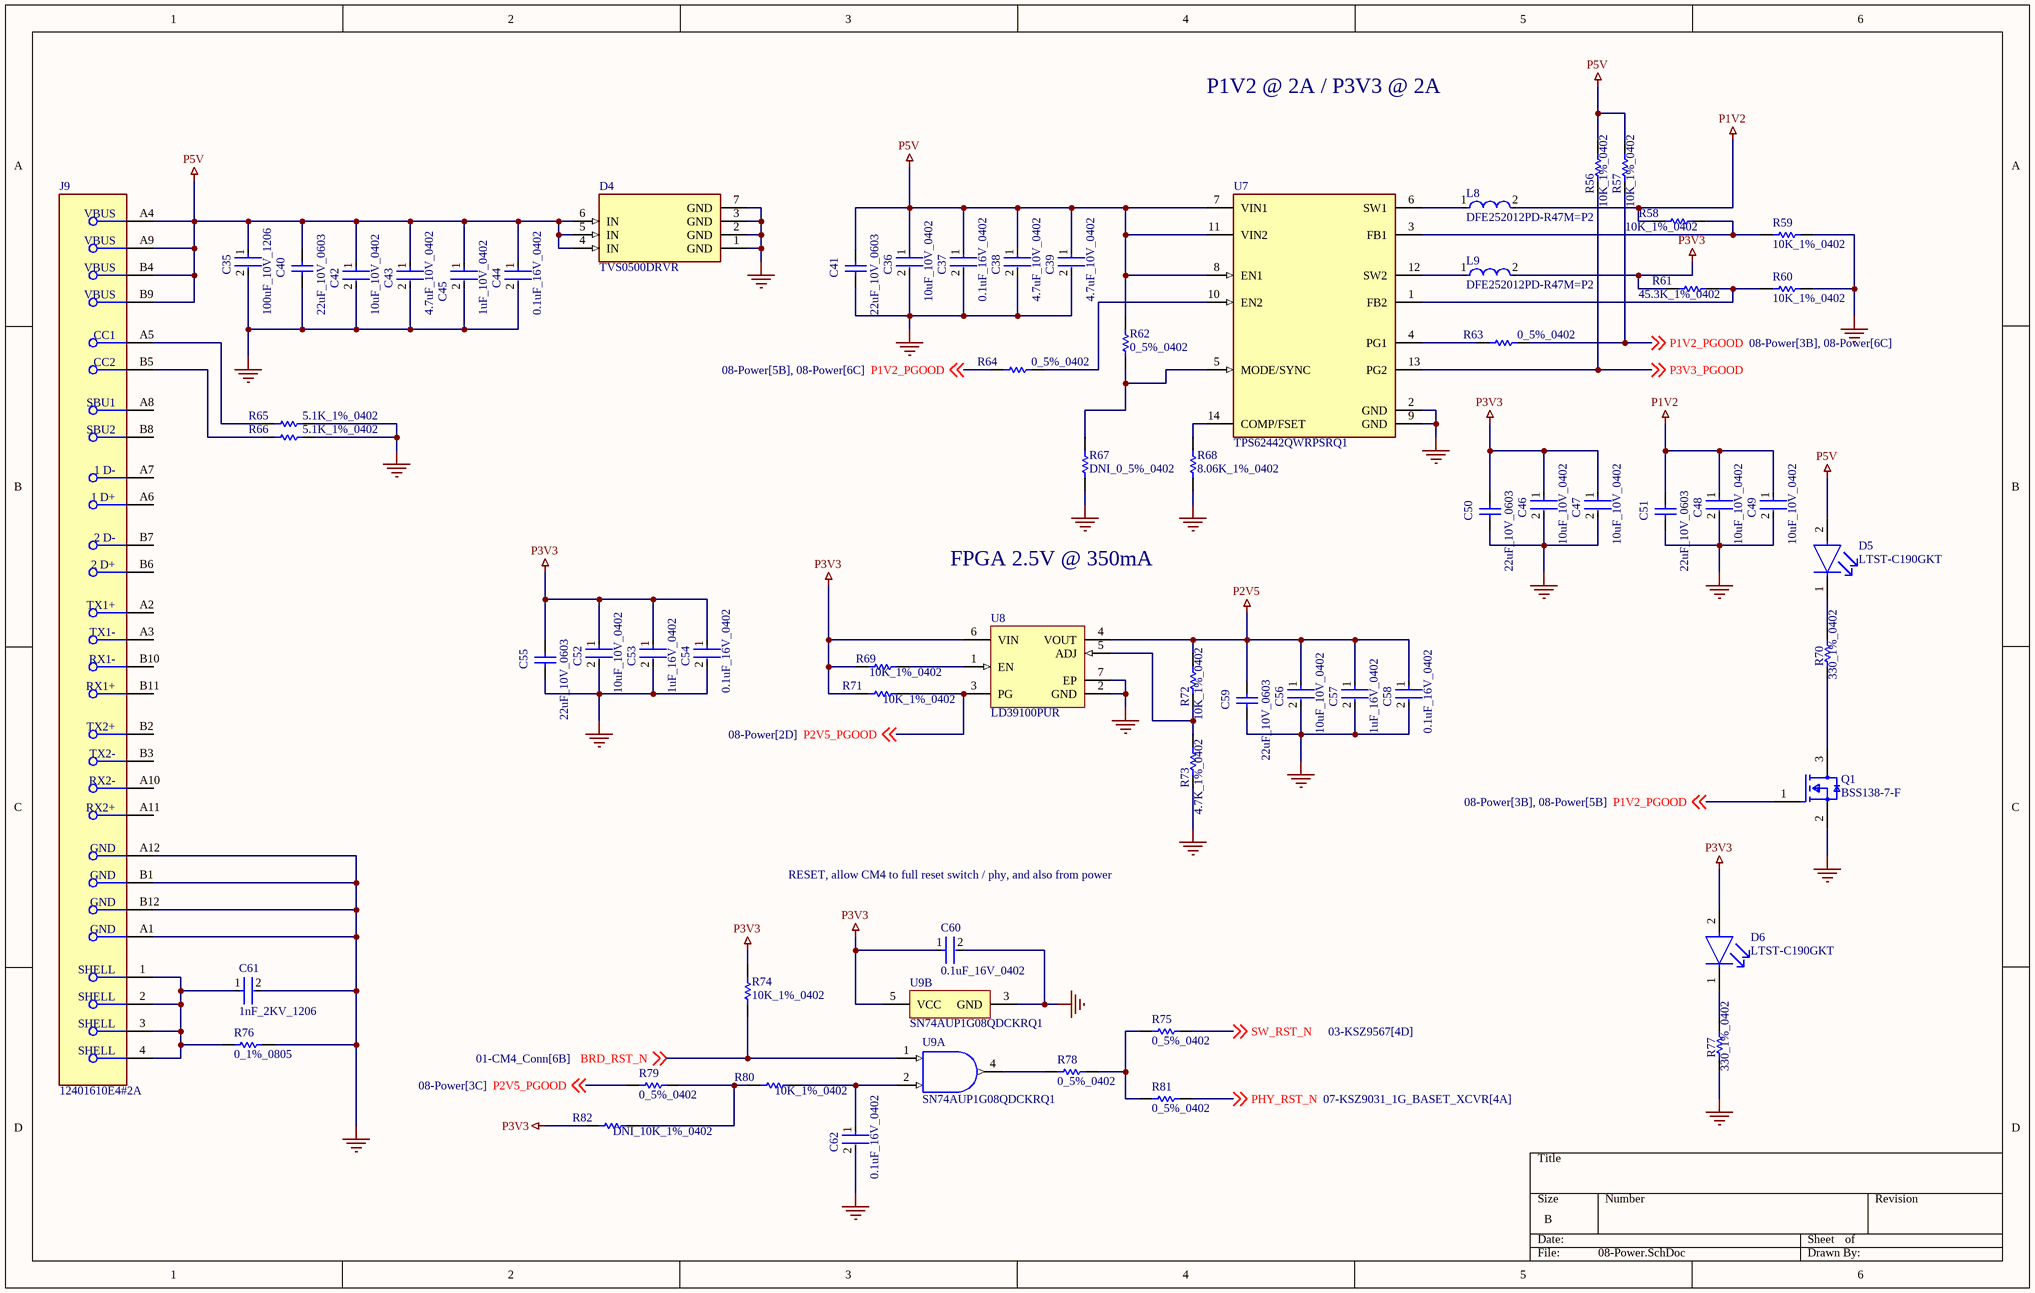
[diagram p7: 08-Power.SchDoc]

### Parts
C35  100uF_10V_1206  [FP-C3216-160-0_3-IPC_C]
C36  10uF_10V_0402  [FP-CL05A106MP5NUNC-MFG]
C37  0.1uF_16V_0402  [FP-C0402-BB-MFG]
C38  4.7uF_10V_0402  [FP-C1005-050-0_15-MFG]
C39  4.7uF_10V_0402  [FP-C1005-050-0_15-MFG]
C40  22uF_10V_0603  [CAPC1608X100X20ML10]
C41  22uF_10V_0603  [CAPC1608X100X20ML10]
C42  10uF_10V_0402  [FP-CL05A106MP5NUNC-MFG]
C43  4.7uF_10V_0402  [FP-C1005-050-0_15-MFG]
C44  0.1uF_16V_0402  [FP-C0402-BB-MFG]
C45  1uF_10V_0402  [FP-CL511-IPC_C]
C46  10uF_10V_0402  [FP-CL05A106MP5NUNC-MFG]
C47  10uF_10V_0402  [FP-CL05A106MP5NUNC-MFG]
C48  10uF_10V_0402  [FP-CL05A106MP5NUNC-MFG]
C49  10uF_10V_0402  [FP-CL05A106MP5NUNC-MFG]
C50  22uF_10V_0603  [CAPC1608X100X20ML10]
C51  22uF_10V_0603  [CAPC1608X100X20ML10]
C52  10uF_10V_0402  [FP-CL05A106MP5NUNC-MFG]
C53  1uF_16V_0402  [FP-0402-L_1_0_0_05-W_0_5-IPC_A]
C54  0.1uF_16V_0402  [FP-C0402-BB-MFG]
C55  22uF_10V_0603  [CAPC1608X100X20ML10]
C56  10uF_10V_0402  [FP-CL05A106MP5NUNC-MFG]
C57  1uF_16V_0402  [FP-0402-L_1_0_0_05-W_0_5-IPC_A]
C58  0.1uF_16V_0402  [FP-C0402-BB-MFG]
C59  22uF_10V_0603  [CAPC1608X100X20ML10]
C60  0.1uF_16V_0402  [FP-C0402-BB-MFG]
C61  1nF_2KV_1206  [FP-CC1206-0_3-1_45-IPC_C]
C62  0.1uF_16V_0402  [FP-C0402-BB-MFG]
D4  TVS0500DRVR  [FP-DRV0006A-MFG]
D5  LTST-C190GKT  [FP-LTST-C190GKT-MFG]
D6  LTST-C190GKT  [FP-LTST-C190GKT-MFG]
J9  12401610E4#2A  [FP-12401610E4#2A-MFG]
L8  DFE252012PD-R47M=P2  [FP-DFE252012C-IPC_A]
L9  DFE252012PD-R47M=P2  [FP-DFE252012C-IPC_A]
Q1  BSS138-7-F  [FP-SOT23_Standard-MFG]
R56  10K_1%_0402  [RESC1005X40X25NL10T10]
R57  10K_1%_0402  [RESC1005X40X25NL10T10]
R58  10K_1%_0402  [RESC1005X40X25NL10T10]
R59  10K_1%_0402  [RESC1005X40X25NL10T10]
R60  10K_1%_0402  [RESC1005X40X25NL10T10]
R61  45.3K_1%_0402  [RESC0402(1005)_L]
R62  0_5%_0402  [RESC1005X40X25NL05T10]
R63  0_5%_0402  [RESC1005X40X25NL05T10]
R64  0_5%_0402  [RESC1005X40X25NL05T10]
R65  5.1K_1%_0402  [RESC1005X40X25NL05T10]
R66  5.1K_1%_0402  [RESC1005X40X25NL05T10]
R67  DNI_0_5%_0402  [RESC1005X40X25NL05T10]  (no BOM)
R68  8.06K_1%_0402  [RESC1005X40X25ML05T05]
R69  10K_1%_0402  [RESC1005X40X25NL10T10]
R70  330_1%_0402  [RESC1005X40X25NL10T10]
R71  10K_1%_0402  [RESC1005X40X25NL10T10]
R72  10K_1%_0402  [RESC1005X40X25NL10T10]
R73  4.7K_1%_0402  [RESC1005X40X25NL10T10]
R74  10K_1%_0402  [RESC1005X40X25NL10T10]
R75  0_5%_0402  [RESC1005X40X25NL05T10]
R76  0_1%_0805  [RESC2013X60X35NL10T20]
R77  330_1%_0402  [RESC1005X40X25NL10T10]
R78  0_5%_0402  [RESC1005X40X25NL05T10]
R79  0_5%_0402  [RESC1005X40X25NL05T10]
R80  10K_1%_0402  [RESC1005X40X25NL10T10]
R81  0_5%_0402  [RESC1005X40X25NL05T10]
R82  DNI_10K_1%_0402  [RESC1005X40X25NL10T10]  (no BOM)
U7  TPS62442QWRPSRQ1  [FP-RQR0014A-MFG]
U8  LD39100PUR  [DFN6D_M]
U9  SN74AUP1G08QDCKRQ1  [DCK0005A_L]  (parts A,B of 2)

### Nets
GND: C35.2 C36.2 C37.2 C38.2 C39.2 C40.1 C41.1 C42.2 C43.2 C44.2 C45.2 C46.2 C47.2 C48.2 C49.2 C50.1 C51.1 C52.2 C53.2 C54.2 C55.1 C56.2 C57.2 C58.2 C59.1 C60.2 C61.2 C62.2 D4.1(GND) D4.2(GND) D4.3(GND) D4.7(GND) J9.A1(GND) J9.A12(GND) J9.B1(GND) J9.B12(GND) Q1.2(S) R59.1 R60.1 R65.2 R66.2 R67.1 R68.1 R73.1 R76.2 R77.1 U7.2(GND) U7.9(GND) U8.2(GND) U8.7(EP) U9.3(GND)
P1V2: C48.1 C49.1 C51.2 L8.2 R58.2
P2V5: C56.1 C57.1 C58.1 C59.2 R72.2 U8.4(VOUT)
P3V3: C46.1 C47.1 C50.2 C52.1 C53.1 C54.1 C55.2 C60.1 D6.2(A) L9.2 R61.1 R69.2 R71.2 R74.1 R82.2 U8.6(VIN) U9.5(VCC)
P5V: C35.1 C36.1 C37.1 C38.1 C39.1 C40.2 C41.2 C42.1 C43.1 C44.1 C45.1 D4.4(IN) D4.5(IN) D4.6(IN) D5.2(A) J9.A4(VBUS) J9.A9(VBUS) J9.B4(VBUS) J9.B9(VBUS) R56.2 R57.2 R62.2 U7.7(VIN1) U7.8(EN1) U7.11(VIN2)
BRD_RST_N: R74.2 U9.1(A) ; off-sheet BRD_RST_N
P1V2_PGOOD: Q1.1(G) R57.1 R63.2 R64.1 ; off-sheet P1V2_PGOOD
P2V5_PGOOD: R71.1 R79.2 U8.3(PG) ; off-sheet P2V5_PGOOD
P3V3_PGOOD: R56.1 U7.13(PG2) ; off-sheet P3V3_PGOOD
PHY_RST_N: R81.1 ; off-sheet PHY_RST_N
SW_RST_N: R75.1 ; off-sheet SW_RST_N
NetC61_1: C61.1 J9.1(SHELL) J9.2(SHELL) J9.3(SHELL) J9.4(SHELL) R76.1
NetC62_1: C62.1 R80.1 U9.2(B)
NetD5_1: D5.1(C) R70.2
NetD6_1: D6.1(C) R77.2
NetJ9_A5: J9.A5(CC1) R65.1
NetJ9_B5: J9.B5(CC2) R66.1
NetL8_1: L8.1 U7.6(SW1)
NetL9_1: L9.1 U7.12(SW2)
NetQ1_3: Q1.3(D) R70.1
NetR58_1: R58.1 R59.2 U7.3(FB1)
NetR60_2: R60.2 R61.2 U7.1(FB2)
NetR62_1: R62.1 R67.2 U7.5(MODE/SYNC)
NetR63_1: R63.1 U7.4(PG1)
NetR64_2: R64.2 U7.10(EN2)
NetR68_2: R68.2 U7.14(COMP/FSET)
NetR69_1: R69.1 U8.1(EN)
NetR72_1: R72.1 R73.2 U8.5(ADJ)
NetR75_2: R75.2 R78.1 R81.2
NetR78_2: R78.2 U9.4(Y)
NetR79_1: R79.1 R80.2 R82.1

Not connected (* = marked no-connect by the designer): J9 A2(TX1+) A3(TX1-) A6(1_D+) A7(1_D-) A8(SBU1) A10(RX2-) A11(RX2+) B2(TX2+) B3(TX2-) B6(2_D+) B7(2_D-) B8(SBU2) B10(RX1-) B11(RX1+)

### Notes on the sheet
- P1V2 @ 2A / P3V3 @ 2A
- FPGA 2.5V @ 350mA
- RESET, allow CM4 to full reset switch / phy, and also from power

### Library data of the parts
C35 = CMP-2000-05396-3: Multilayer Ceramic Capacitors 100uF ±20% 10V X5R SMD 1206
C36 C42 C46-C49 C52 C56 = CMP-13271-000002-1: as C13 on sheet 02-Clocks
C37 C44 C54 C58 C60 C62 = CMP-1034-02068-3: as C16 on sheet 02-Clocks
C38 C39 C43 = CMP-2000-05997-2: CAP CER 4.7UF 10V X5R 0402; Dielectric Material: Ceramic; Tolerance: 10%
C40 C41 C50 C51 C55 C59 = CMP-2000-05441-1: Chip Capacitor, 22 uF, +/- 20%, 10 V, -55 to 85 degC, 0603 (1608 Metric), RoHS, Tape and Reel; Manufacturer: TDK; PCN Part Number: MLCCPartNumberChange30/Nov/2012; Voltage - Rated: 10V; Product Training Modules: CSeriesGeneralApplicationsSEAT,CCV,andTVCLDesignToolsGuidetoReplacinganElectrolyticCapacitorwithanMLCC; Other Names: 445-9077-1; Design Resources: 20WNon-IsolatedBuckLEDDriverUsingPLLNK460KG; Online Catalog: CSeries,GeneralPurpose; Capacitance: 22µF; Temperature Coefficient: X5R; Kits: 445-9014-KIT-ND-KITMLCC100PF-22UF060310-50V
C45 = CMP-13271-001936-1: Cap Ceramic 1uF 10V X5R ±10% SMD 0402 +85°C Paper T/R
C53 C57 = CMP-14477-000104-2: as C14 on sheet 02-Clocks
C61 = CMP-2000-05436-2: CAP CER 1000PF 2KV X7R 1206; Capacitance: 1nF; Insulation Resistance: 10GR; Dissipation Factor: 2.5%; Tolerance: 10%
D4 = CMP-04989-000008-1: UNIDIR PRECISION SURGE DIODE; Peak Pulse Power: 400W; Power Line Protection: No; Reverse Standoff Voltage: 5V; Min Breakdown Voltage: 7.5V; Peak Pulse Current: 43A; Number of Unidirectional Channels: 1; Clamping Voltage: 9.5V
D5 D6 = CMP-22017-000005-2: as D1 on sheet 01-CM4_Conn
J9 = CMP-02355-000003-1: CONN RCP USB3.1 TYPEC 24P SMD RA; Connector Type: USB; Number of Contacts: 24; Gender: Receptacle
L8 L9 = CMP-06042-015149-1: Shielded Wirewound Inductor 0.47uH 20% 4000mA 0.027Ω 1008 (2520)
Q1 = CMP-2000-04930-2: NexarPartId: 335900; Voltage: 50V; Fall Time: 25ns; Number of Elements: 1; Turn-On Delay Time: 20ns; Drain to Source Resistance: 1.4Ω; Element Configuration: Single; Max Power Dissipation: 300mW; Current Rating: 200mA; Max Junction Temperature (Tj): 150°C; Input Capacitance: 50pF; Threshold Voltage: 1.2V; Current: 2A; Rds On Max: 3.5Ω; Rise Time: 10ns; Gate to Source Voltage (Vgs): 20V
R56-R60 R69 R71 R72 R74 R80 R82 = CMP-2002-04694-1: as R52 on sheet 01-CM4_Conn
R61 = CMP-1011-00697-1: 45K3 0.063W 1% 0402 (1005 Metric)  SMD; Case-EIA: 0402; Case-Metric: 1005; Value: 45300.00 Ohm
R62-R64 R67 R75 R78 R79 R81 = CMP-2002-06457-1: as R29 on sheet 02-Clocks
R65 R66 = CMP-2002-07753-1: Part Number: RC0402FR-075K1L; Manufacturer: Yageo / Phycomp
R68 = CMP-2002-00253-3: Chip Resistor, 8.06 KOhm, +/- 1%, 63 mW, -55 to 155 degC, 0402 (1005 Metric), RoHS, Tape and Reel; PartNumber: CRCW04028K06FKED; Manufacturer: Basic Passives; Case\/Package: 0402; Power Rating: 63 mW; Voltage Rating: 50 V
R70 R77 = CMP-2002-05853-1: as R26 on sheet 01-CM4_Conn
R73 = CMP-2002-05217-1: as R9 on sheet 01-CM4_Conn
R76 = CMP-2001-04478-1: Manufacturer: Yageo; Part Number: AC0805FR-070RL
U7 = CMP-04918-000654-1: Adjustable-Frequency Dual Step-Down Converter, 2.7-6V VIN, 0.6-5.5V 2A VOUT, VQFN-HR14
U8 = CMP-0244-00287-1: 1 A Low Quiescent Current Low Noise Voltage Regulator, Adjustable from 0.8V, 6-Pin VFDFPN, Tape and Reel
U9 = CMP-0859-00286-3: Automotive Catalog Low-Power Single 2-Input Positive-AND Gate, DCK0005A, LARGE T&R; Manufacturer: Texas Instruments; Generic Part Number: SN74AUP1G08-Q1; VCC(Min)(V): 0.8; Voltage(Nom)(V): 0.8,1.2,1.5,1.8,2.5,3.3; Input Type: CMOS; F @ Nom Voltage(Max)(Mhz): 100; tpd @ Nom Voltage(Max)(ns): 32.8,20.9,14.2,11,7.6,6.2; Gate Type: AND; Technology Family: AUP; VCC(Max)(V): 3.6; ICC @ Nom Voltage(Max)(mA): 0.0009; Output Drive (IOL/IOH)(Max)(mA): 20/-20; Schmitt Trigger: No; Bits(#): 1; Logic: True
